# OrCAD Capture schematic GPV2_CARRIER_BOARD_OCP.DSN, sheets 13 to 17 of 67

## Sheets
13 013 MEZZ CONN EXTENSION: size C
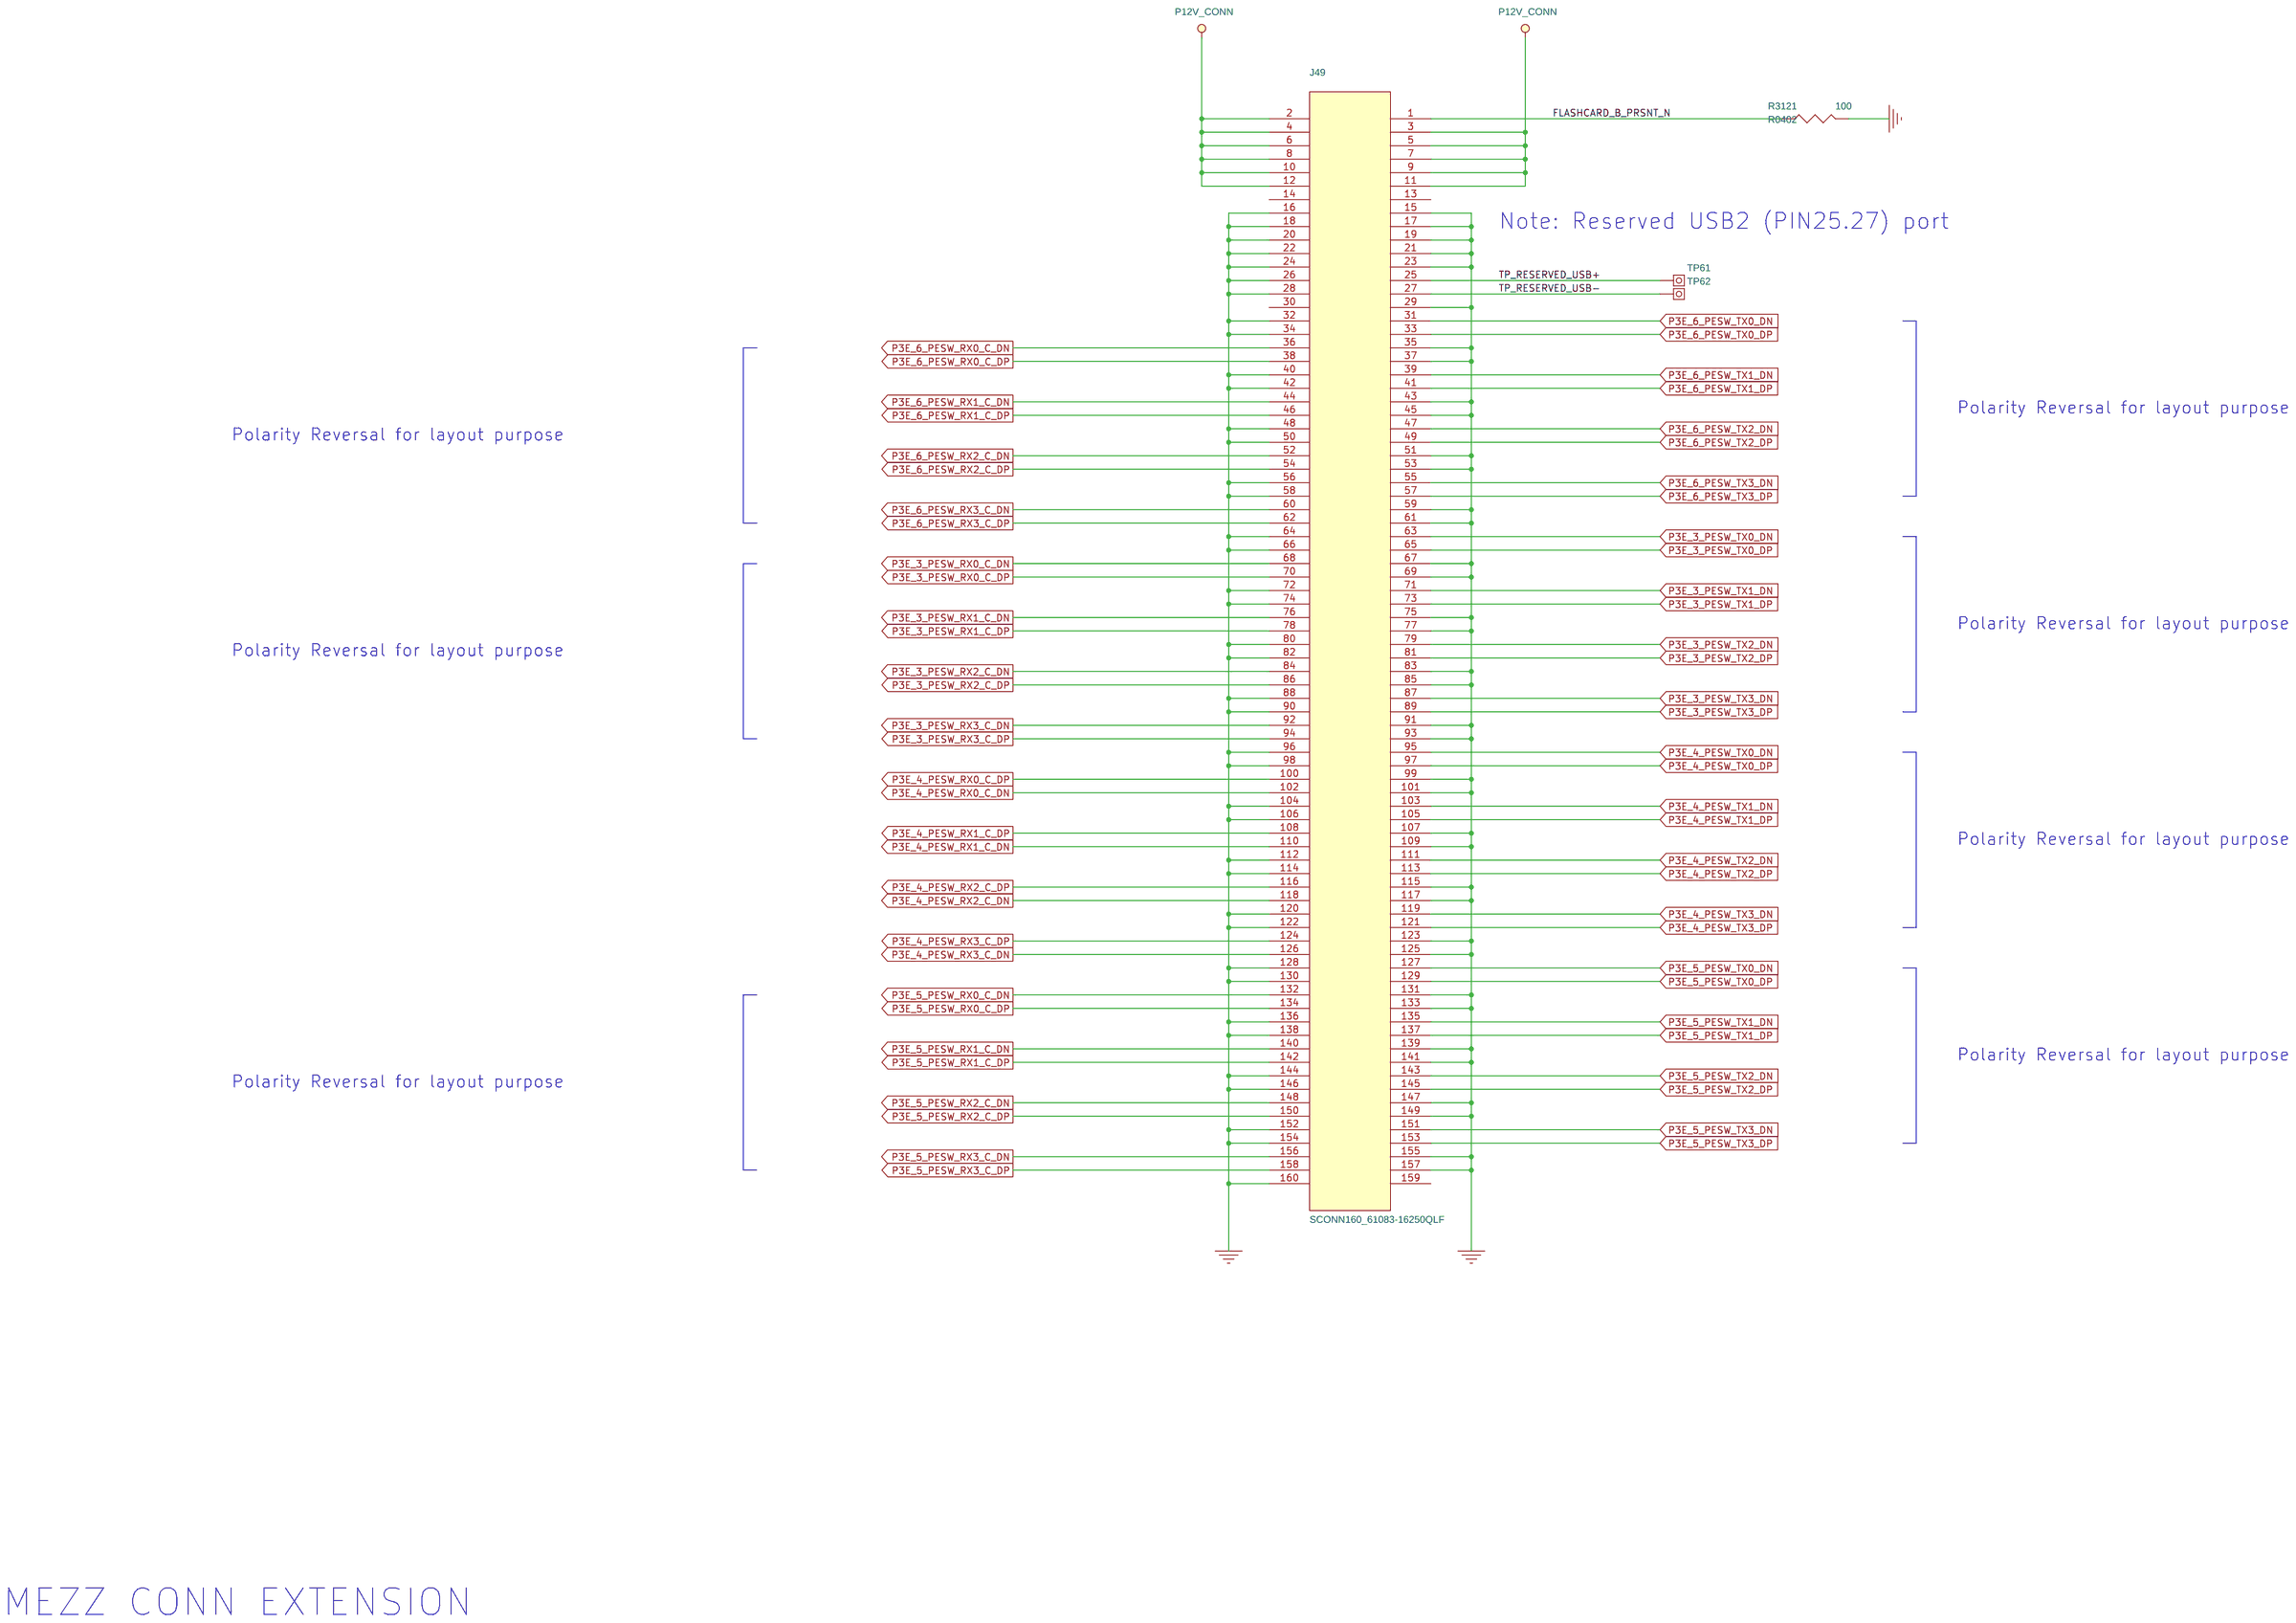
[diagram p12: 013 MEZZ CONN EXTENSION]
14 014 PCIE SWITCH (STACK1-2): size C
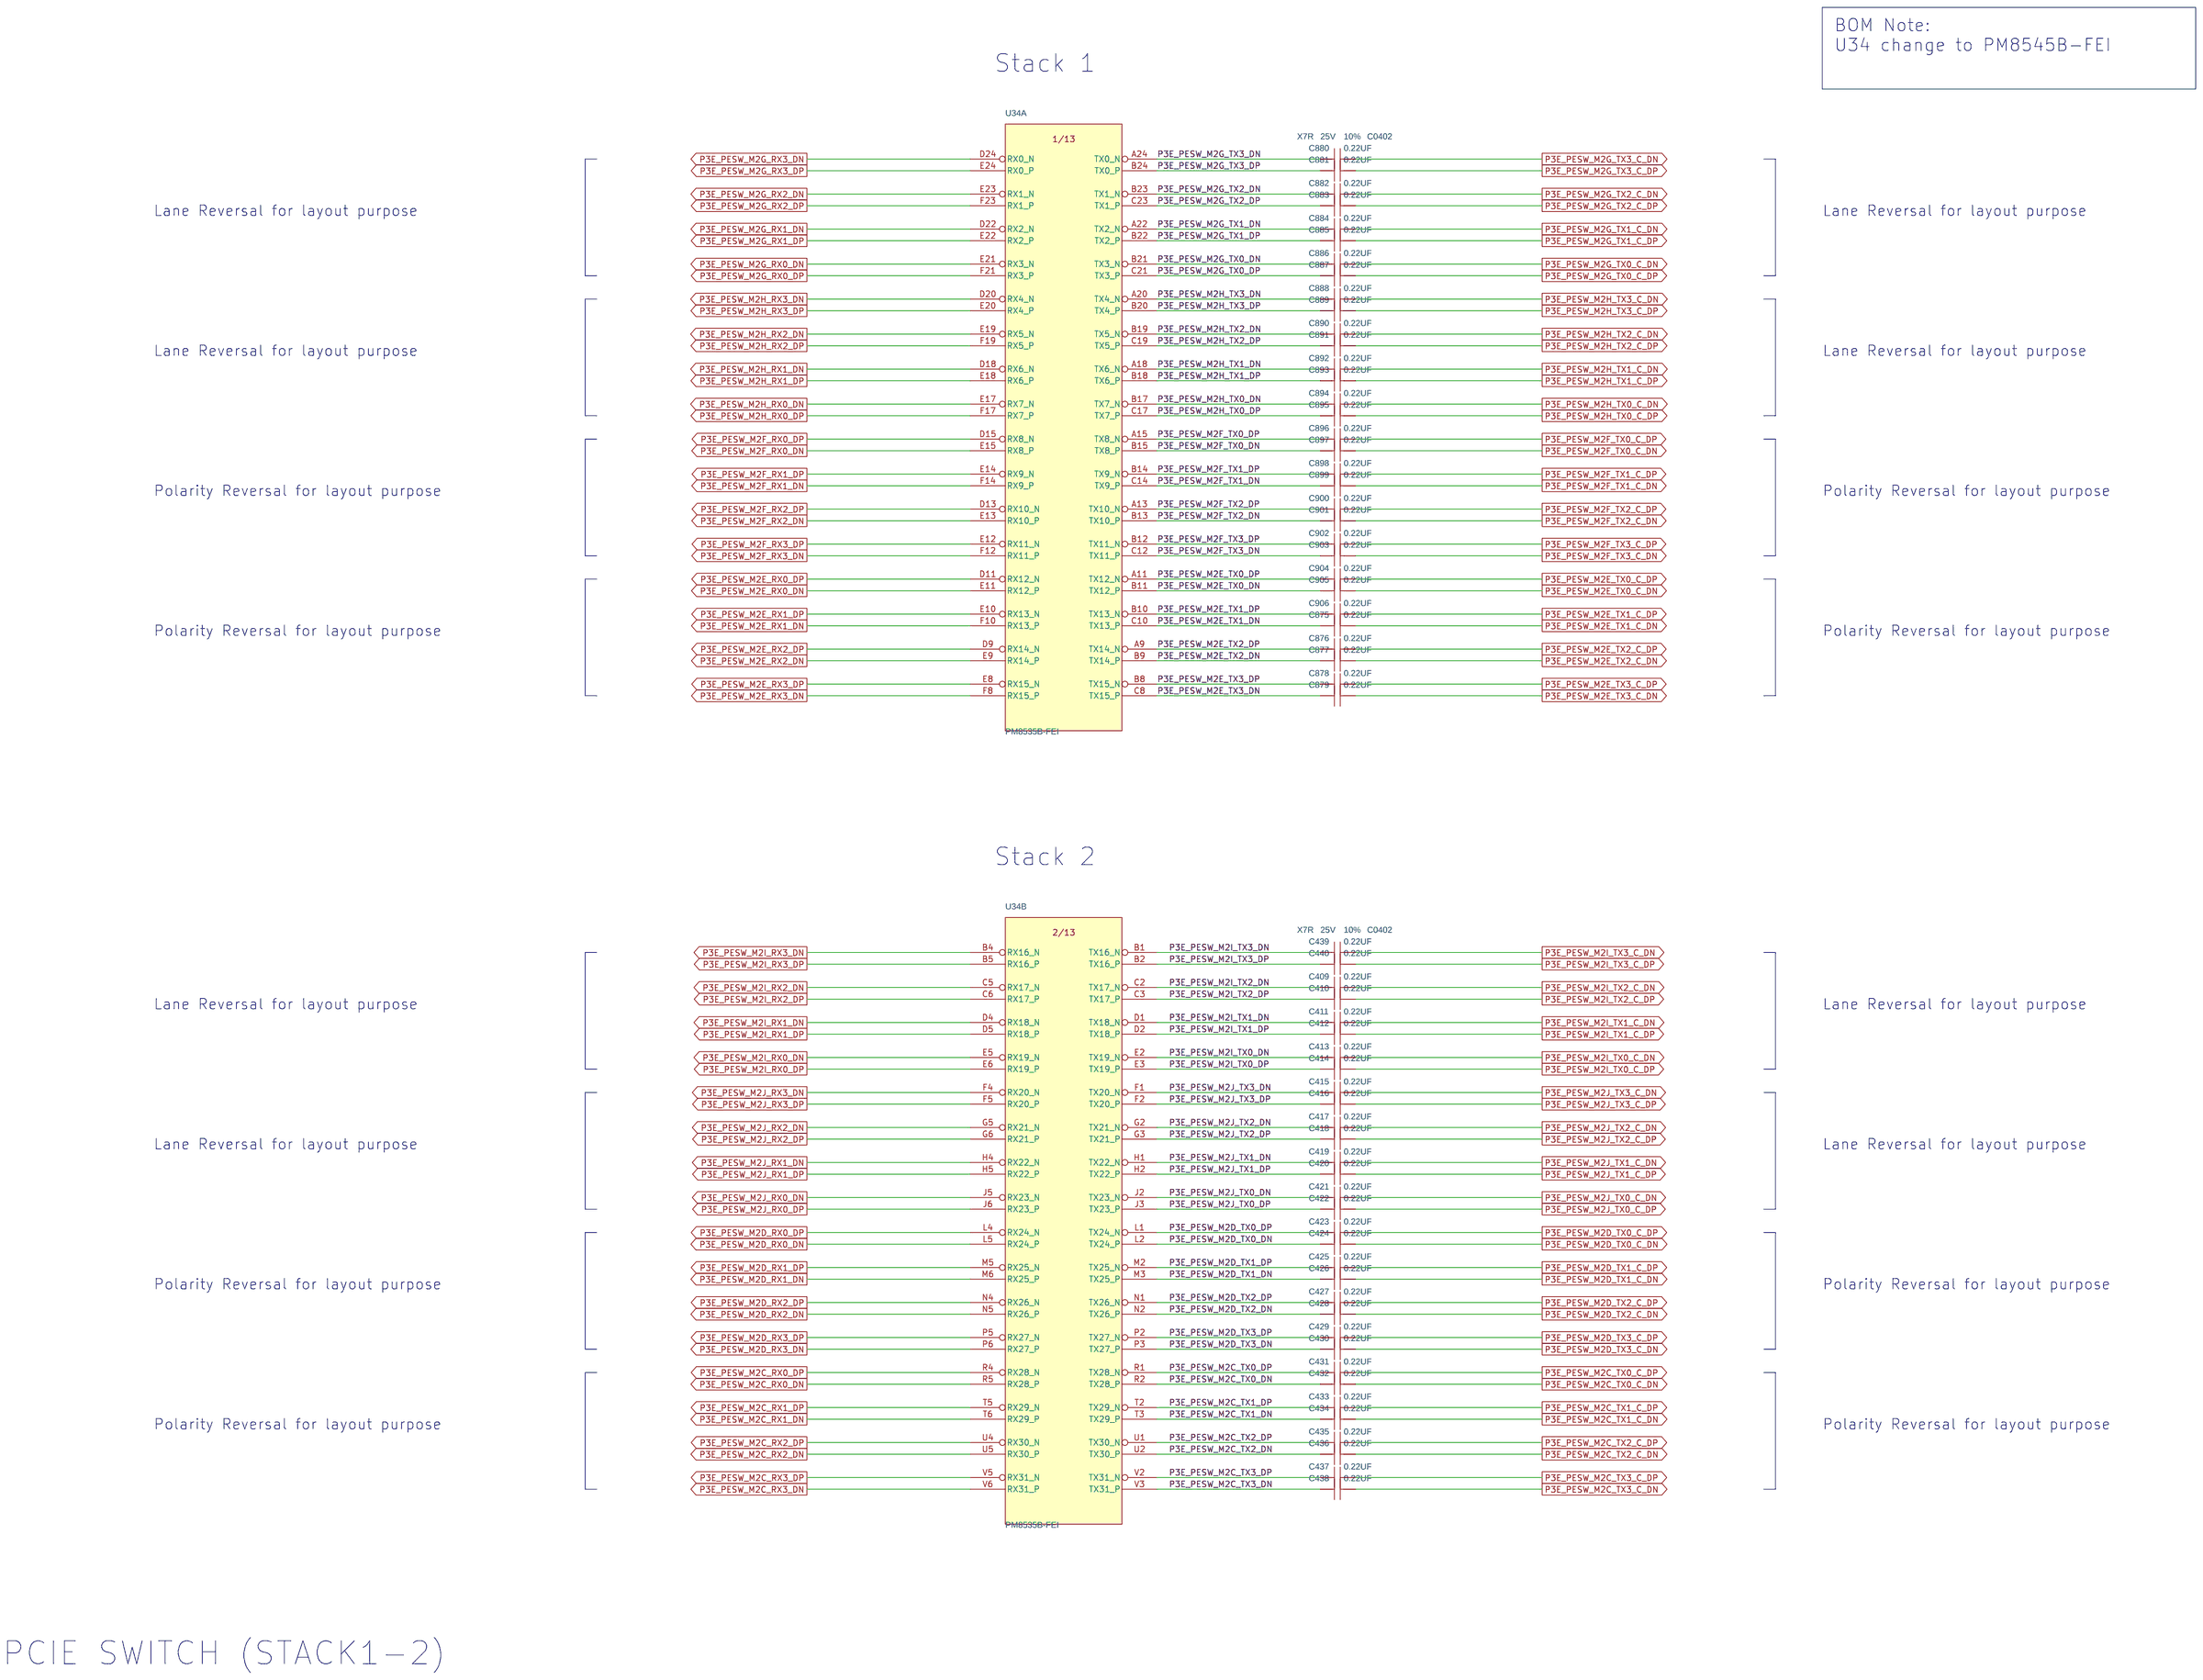
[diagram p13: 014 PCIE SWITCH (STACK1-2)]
15 015 PCIE SWITCH (STACK3-4): size C
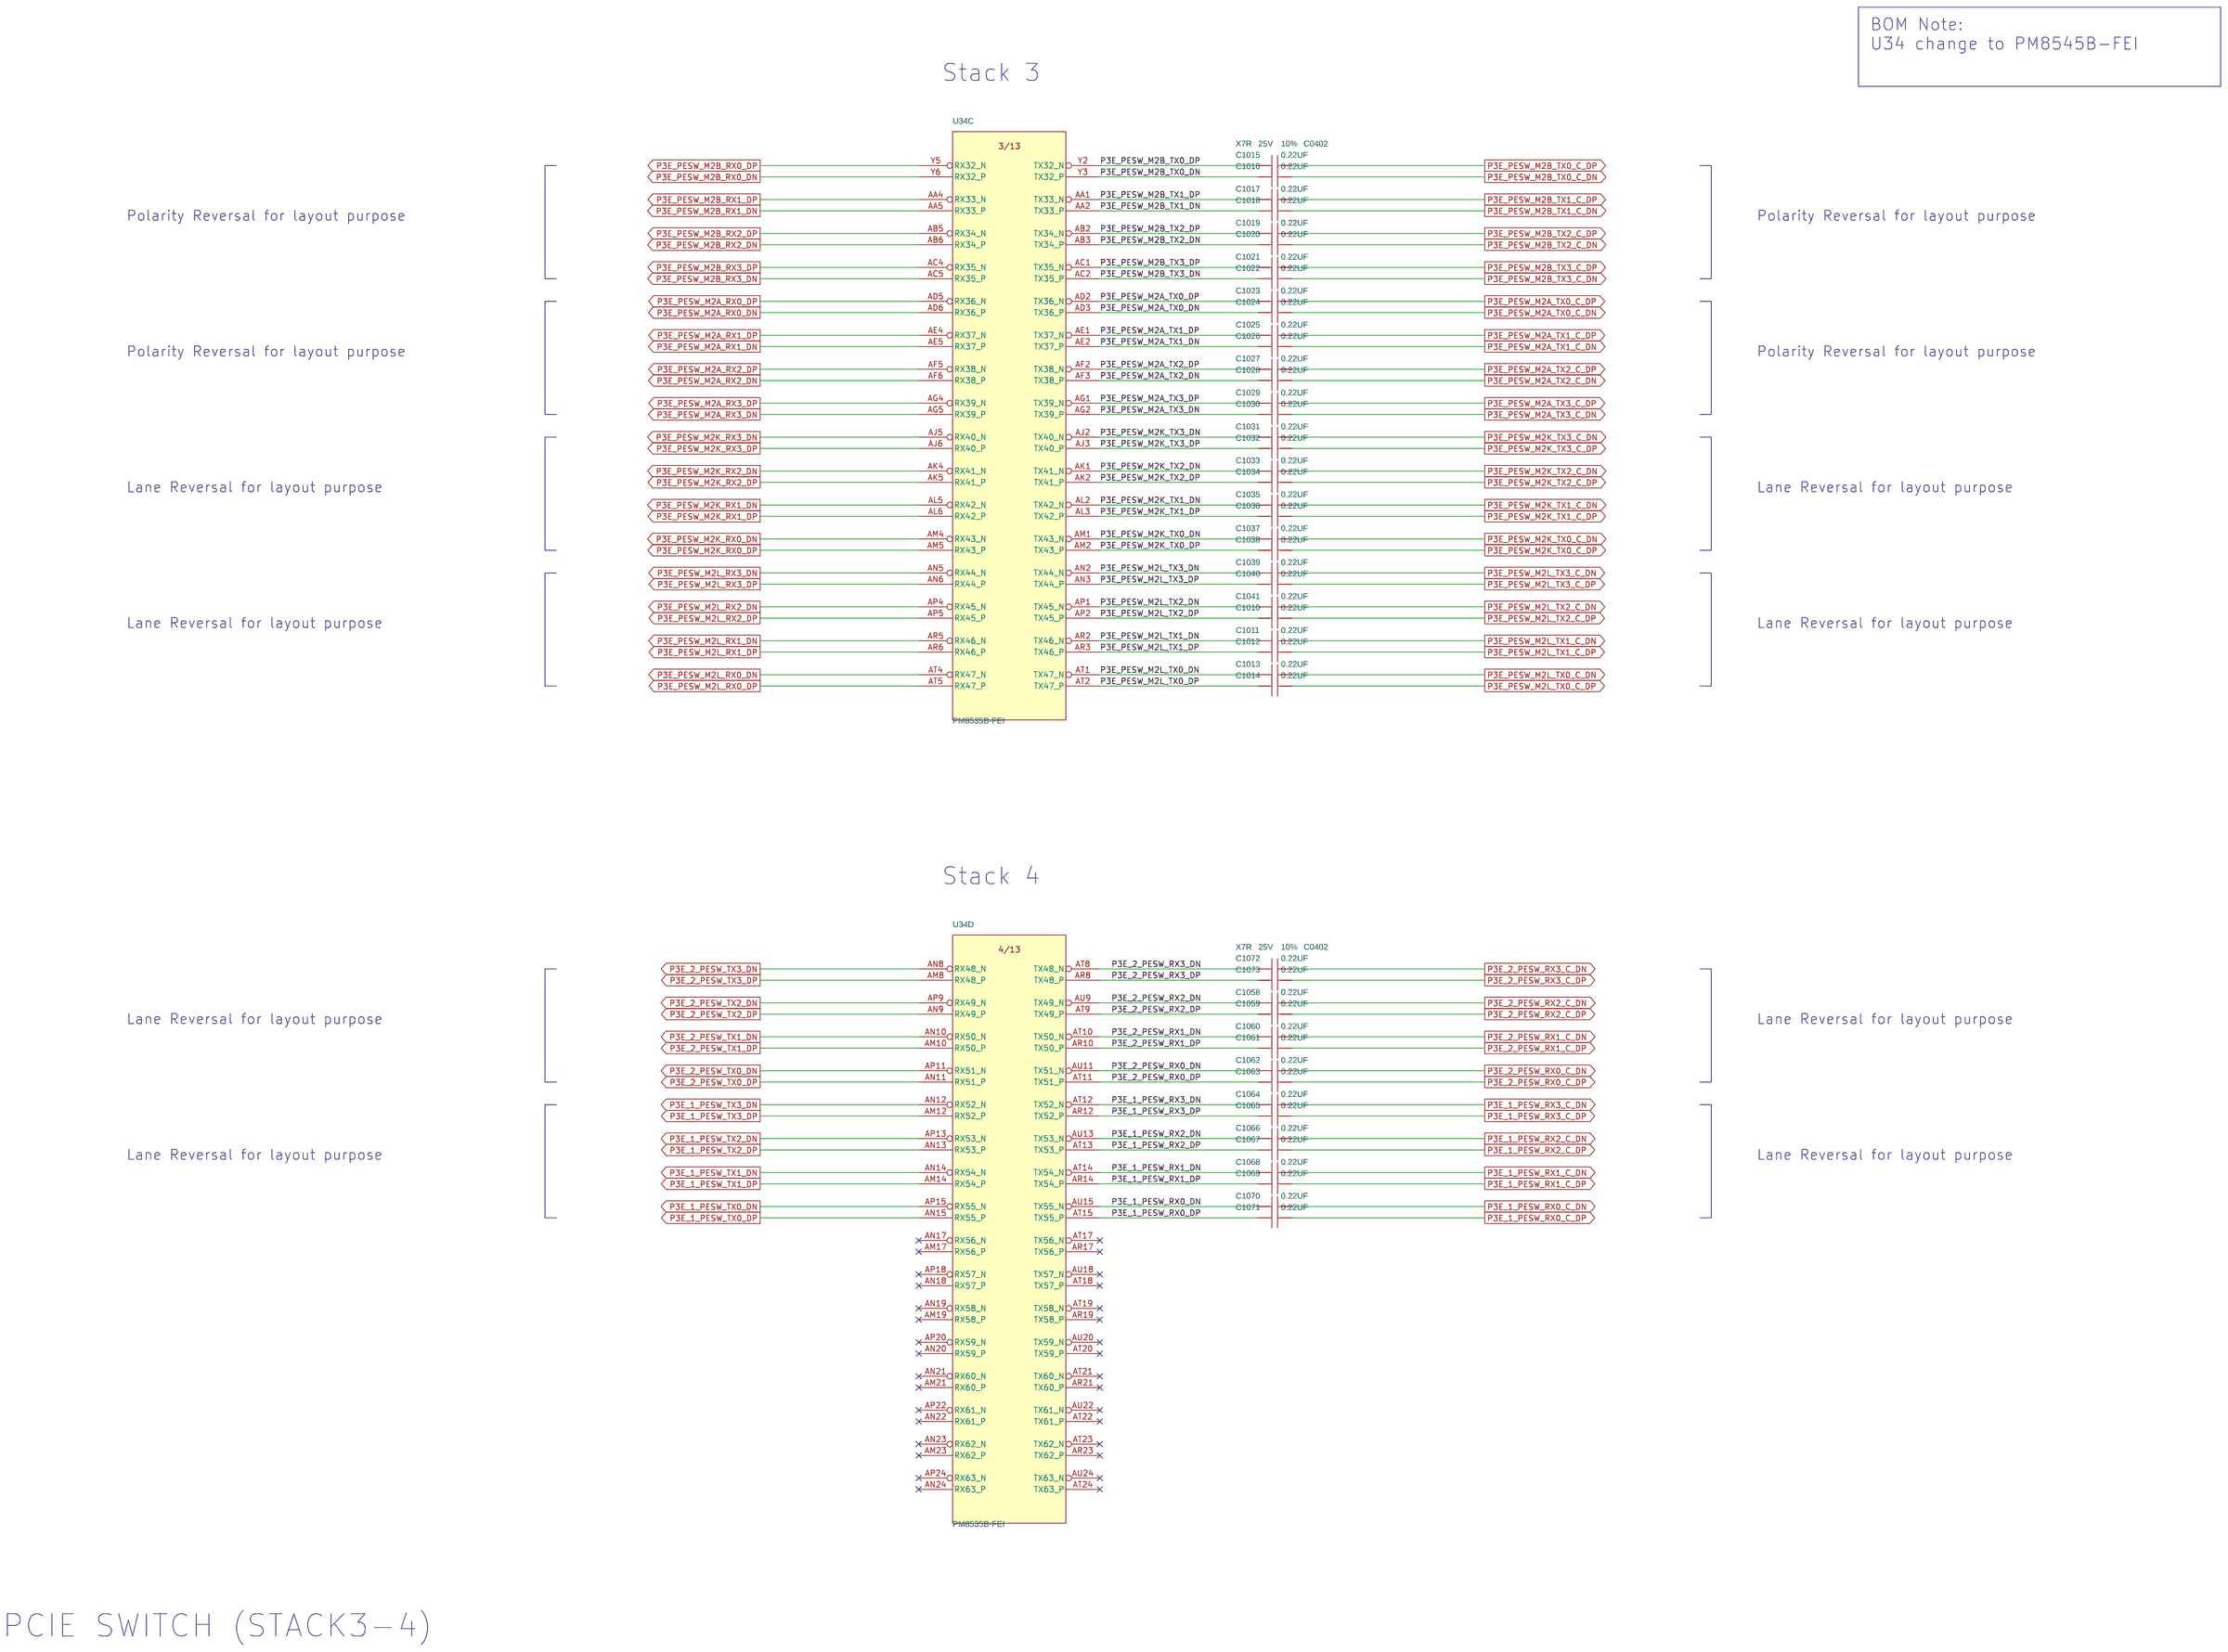
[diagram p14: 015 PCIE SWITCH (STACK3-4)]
16 016 PCIE SWITCH (STACK5): size C
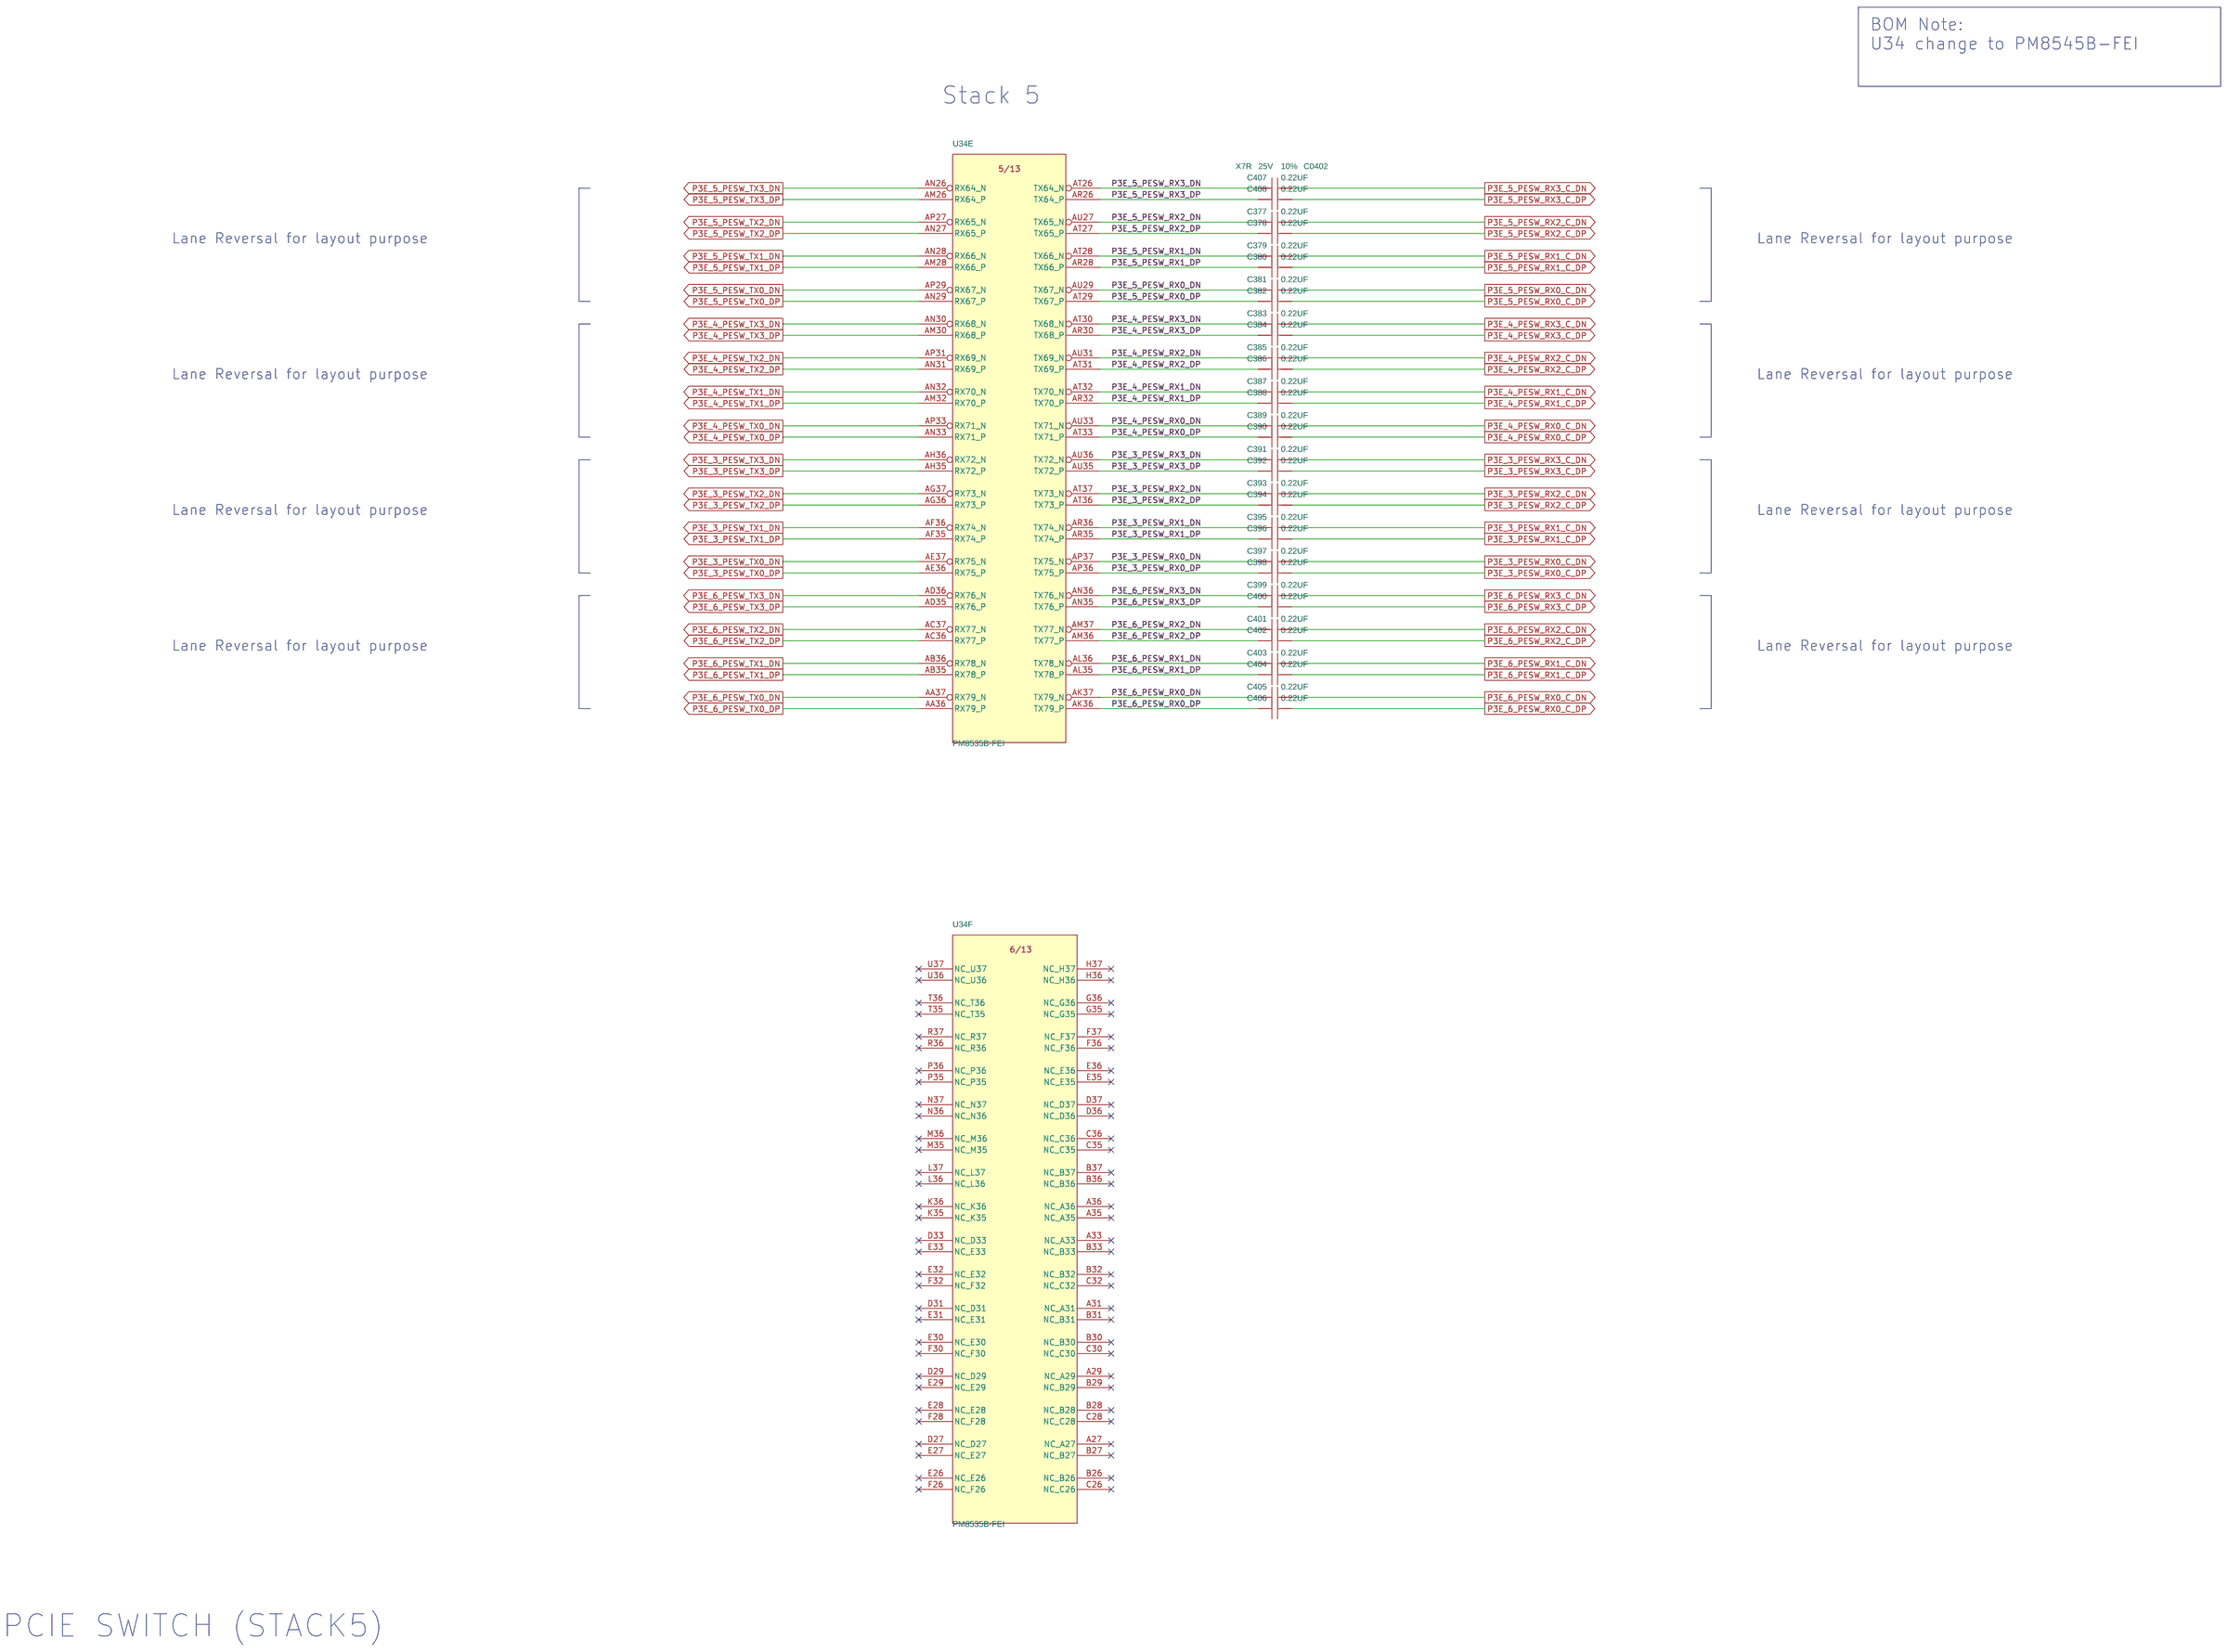
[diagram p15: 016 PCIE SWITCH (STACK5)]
17 018 PCIE SWITCH (GPIO): size C
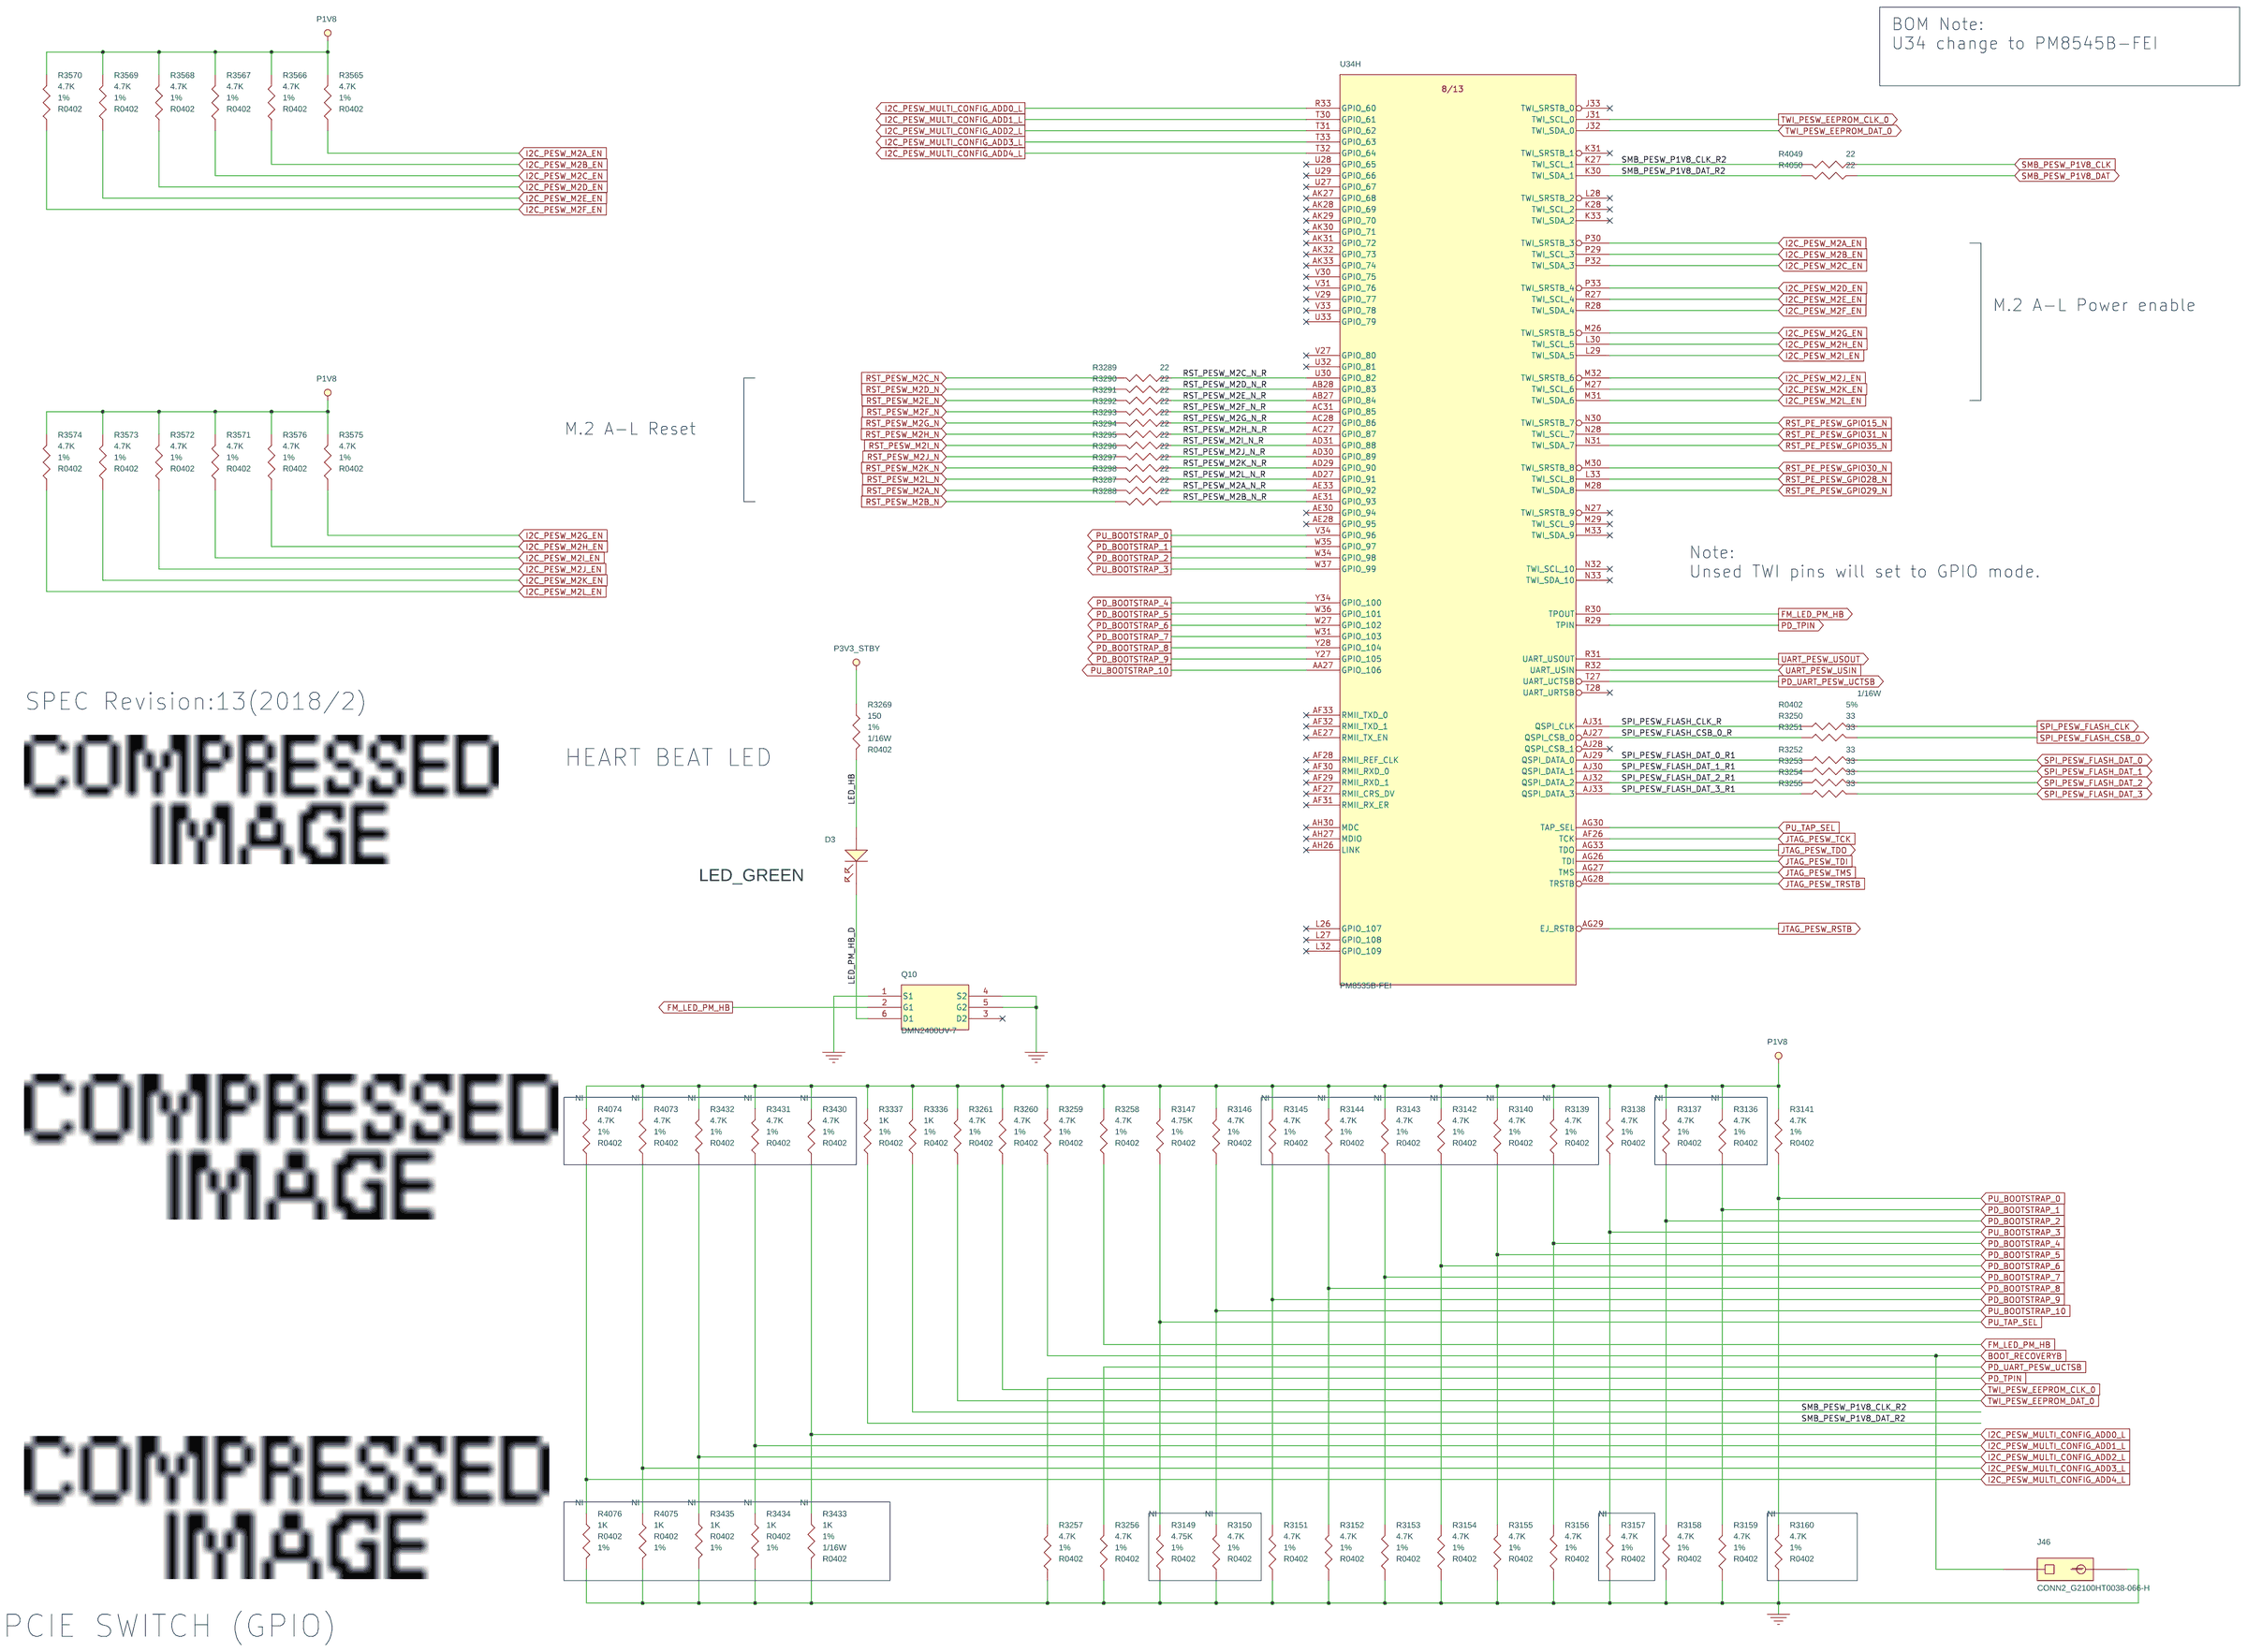
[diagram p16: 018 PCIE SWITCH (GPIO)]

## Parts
sheet 013 MEZZ CONN EXTENSION
J49  SCONN160_61083-16250QLF  [CON_M160S2H2D_P0-8W4-4_LUV]
R3121  100  [R0402]
TP61  TP  [TP26D10]
TP62  TP  [TP26D10]
sheet 014 PCIE SWITCH (STACK1-2)
C409  0.22UF  [C0402]
C410  0.22UF  [C0402]
C411  0.22UF  [C0402]
C412  0.22UF  [C0402]
C413  0.22UF  [C0402]
C414  0.22UF  [C0402]
C415  0.22UF  [C0402]
C416  0.22UF  [C0402]
C417  0.22UF  [C0402]
C418  0.22UF  [C0402]
C419  0.22UF  [C0402]
C420  0.22UF  [C0402]
C421  0.22UF  [C0402]
C422  0.22UF  [C0402]
C423  0.22UF  [C0402]
C424  0.22UF  [C0402]
C425  0.22UF  [C0402]
C426  0.22UF  [C0402]
C427  0.22UF  [C0402]
C428  0.22UF  [C0402]
C429  0.22UF  [C0402]
C430  0.22UF  [C0402]
C431  0.22UF  [C0402]
C432  0.22UF  [C0402]
C433  0.22UF  [C0402]
C434  0.22UF  [C0402]
C435  0.22UF  [C0402]
C436  0.22UF  [C0402]
C437  0.22UF  [C0402]
C438  0.22UF  [C0402]
C439  0.22UF  [C0402]
C440  0.22UF  [C0402]
C875  0.22UF  [C0402]
C876  0.22UF  [C0402]
C877  0.22UF  [C0402]
C878  0.22UF  [C0402]
C879  0.22UF  [C0402]
C880  0.22UF  [C0402]
C881  0.22UF  [C0402]
C882  0.22UF  [C0402]
C883  0.22UF  [C0402]
C884  0.22UF  [C0402]
C885  0.22UF  [C0402]
C886  0.22UF  [C0402]
C887  0.22UF  [C0402]
C888  0.22UF  [C0402]
C889  0.22UF  [C0402]
C890  0.22UF  [C0402]
C891  0.22UF  [C0402]
C892  0.22UF  [C0402]
C893  0.22UF  [C0402]
C894  0.22UF  [C0402]
C895  0.22UF  [C0402]
C896  0.22UF  [C0402]
C897  0.22UF  [C0402]
C898  0.22UF  [C0402]
C899  0.22UF  [C0402]
C900  0.22UF  [C0402]
C901  0.22UF  [C0402]
C902  0.22UF  [C0402]
C903  0.22UF  [C0402]
C904  0.22UF  [C0402]
C905  0.22UF  [C0402]
C906  0.22UF  [C0402]
sheet 015 PCIE SWITCH (STACK3-4)
C1010  0.22UF  [C0402]
C1011  0.22UF  [C0402]
C1012  0.22UF  [C0402]
C1013  0.22UF  [C0402]
C1014  0.22UF  [C0402]
C1015  0.22UF  [C0402]
C1016  0.22UF  [C0402]
C1017  0.22UF  [C0402]
C1018  0.22UF  [C0402]
C1019  0.22UF  [C0402]
C1020  0.22UF  [C0402]
C1021  0.22UF  [C0402]
C1022  0.22UF  [C0402]
C1023  0.22UF  [C0402]
C1024  0.22UF  [C0402]
C1025  0.22UF  [C0402]
C1026  0.22UF  [C0402]
C1027  0.22UF  [C0402]
C1028  0.22UF  [C0402]
C1029  0.22UF  [C0402]
C1030  0.22UF  [C0402]
C1031  0.22UF  [C0402]
C1032  0.22UF  [C0402]
C1033  0.22UF  [C0402]
C1034  0.22UF  [C0402]
C1035  0.22UF  [C0402]
C1036  0.22UF  [C0402]
C1037  0.22UF  [C0402]
C1038  0.22UF  [C0402]
C1039  0.22UF  [C0402]
C1040  0.22UF  [C0402]
C1041  0.22UF  [C0402]
C1058  0.22UF  [C0402]
C1059  0.22UF  [C0402]
C1060  0.22UF  [C0402]
C1061  0.22UF  [C0402]
C1062  0.22UF  [C0402]
C1063  0.22UF  [C0402]
C1064  0.22UF  [C0402]
C1065  0.22UF  [C0402]
C1066  0.22UF  [C0402]
C1067  0.22UF  [C0402]
C1068  0.22UF  [C0402]
C1069  0.22UF  [C0402]
C1070  0.22UF  [C0402]
C1071  0.22UF  [C0402]
C1072  0.22UF  [C0402]
C1073  0.22UF  [C0402]
sheet 016 PCIE SWITCH (STACK5)
C377  0.22UF  [C0402]
C378  0.22UF  [C0402]
C379  0.22UF  [C0402]
C380  0.22UF  [C0402]
C381  0.22UF  [C0402]
C382  0.22UF  [C0402]
C383  0.22UF  [C0402]
C384  0.22UF  [C0402]
C385  0.22UF  [C0402]
C386  0.22UF  [C0402]
C387  0.22UF  [C0402]
C388  0.22UF  [C0402]
C389  0.22UF  [C0402]
C390  0.22UF  [C0402]
C391  0.22UF  [C0402]
C392  0.22UF  [C0402]
C393  0.22UF  [C0402]
C394  0.22UF  [C0402]
C395  0.22UF  [C0402]
C396  0.22UF  [C0402]
C397  0.22UF  [C0402]
C398  0.22UF  [C0402]
C399  0.22UF  [C0402]
C400  0.22UF  [C0402]
C401  0.22UF  [C0402]
C402  0.22UF  [C0402]
C403  0.22UF  [C0402]
C404  0.22UF  [C0402]
C405  0.22UF  [C0402]
C406  0.22UF  [C0402]
C407  0.22UF  [C0402]
C408  0.22UF  [C0402]
sheet 017 PCIE SWITCH (CLOCKS/RESET)
U34  PM8535B-FEI  [BGA1311_1_37-5X37-5]  (sections A,B,C,D,E,F,G,H,I,J,K,L,M)
sheet 018 PCIE SWITCH (GPIO)
D3  LED_GREEN  [LED_1921]
J46  CONN2_G2100HT0038-066-H  [HEADER1X2XJ_H339]
Q10  DMN2400UV-7  [SOT563-6XA]
R3136  4.7K  [R0402]
R3137  4.7K  [R0402]
R3138  4.7K  [R0402]
R3139  4.7K  [R0402]
R3140  4.7K  [R0402]
R3141  4.7K  [R0402]
R3142  4.7K  [R0402]
R3143  4.7K  [R0402]
R3144  4.7K  [R0402]
R3145  4.7K  [R0402]
R3146  4.7K  [R0402]
R3147  4.75K  [R0402]
R3149  4.75K  [R0402]
R3150  4.7K  [R0402]
R3151  4.7K  [R0402]
R3152  4.7K  [R0402]
R3153  4.7K  [R0402]
R3154  4.7K  [R0402]
R3155  4.7K  [R0402]
R3156  4.7K  [R0402]
R3157  4.7K  [R0402]
R3158  4.7K  [R0402]
R3159  4.7K  [R0402]
R3160  4.7K  [R0402]
R3250  33  [R0402]
R3251  33  [R0402]
R3252  33  [R0402]
R3253  33  [R0402]
R3254  33  [R0402]
R3255  33  [R0402]
R3256  4.7K  [R0402]
R3257  4.7K  [R0402]
R3258  4.7K  [R0402]
R3259  4.7K  [R0402]
R3260  4.7K  [R0402]
R3261  4.7K  [R0402]
R3269  150  [R0402]
R3287  22  [R0402]
R3288  22  [R0402]
R3289  22  [R0402]
R3290  22  [R0402]
R3291  22  [R0402]
R3292  22  [R0402]
R3293  22  [R0402]
R3294  22  [R0402]
R3295  22  [R0402]
R3296  22  [R0402]
R3297  22  [R0402]
R3298  22  [R0402]
R3336  1K  [R0402]
R3337  1K  [R0402]
R3430  4.7K  [R0402]
R3431  4.7K  [R0402]
R3432  4.7K  [R0402]
R3433  1K  [R0402]
R3434  1K  [R0402]
R3435  1K  [R0402]
R3565  4.7K  [R0402]
R3566  4.7K  [R0402]
R3567  4.7K  [R0402]
R3568  4.7K  [R0402]
R3569  4.7K  [R0402]
R3570  4.7K  [R0402]
R3571  4.7K  [R0402]
R3572  4.7K  [R0402]
R3573  4.7K  [R0402]
R3574  4.7K  [R0402]
R3575  4.7K  [R0402]
R3576  4.7K  [R0402]
R4049  22  [R0402]
R4050  22  [R0402]
R4073  4.7K  [R0402]
R4074  4.7K  [R0402]
R4075  1K  [R0402]
R4076  1K  [R0402]

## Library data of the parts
J49 = SCONN160_6108316150QLF: CONN SMD HEADER 160P 2R MS(P0.8,H5.7); CLASS: IO; ESD_CDM: N/A; ESD_HBM: N/A; ESD_MM: N/A; MATERIAL: IO; MSD: NA; Manuf_PN: 61083-16250QLF; Manuf_name: AMPHENOL EAST ASIA LIMITED (Amphenol-TCS) (Shangh; Manuftr: APL; PIN_LENGTH_LONG_PIN: 32 MILS; PIN_LENGTH_SHORT_PIN: 32 MILS; Part_Type: *LF_Connector
R3121 = R: RES CHIP 100 1/16W +-5% (0402); CLASS: DISCRETE; MATERIAL: CHIP; Manuf_PN: RR0510S-101-JN; Manuf_name: CYNTEC CO.. LTD.; Manuftr: CYN; Part_Type: *LF_Resistor; TOLERANCE: 5%; WATTAGE: 1/16W
TP61 TP62 = TP: TEST POINT (TP26D10) DIP(DRILL10MILS); ALT_SYMBOLS: TOP:TP26D10;BOTTOM:TP30D10; CLASS: IO; DIP_SMD: DIP; MATERIAL: MISC; Not_insert: NI; Part_Type: Misc
C377-C440 C875-C906 C1010-C1041 C1058-C1073 = CAP_NP: CAP CHIP 0.22U 25V(10%,X7R,0402); CLASS: DISCRETE; MATERIAL: X7R; Manuf_PN: TMK105B7224KV-FR; Manuf_name: TAIYO YUDEN CO.,LTD; Manuftr: TAY; Part_Type: *LF_C0402; TOLERANCE: 10%; VOLTAGE: 25V
U34 = PM8535BFEI: IC CTRL(1311P)PM8535B-FEI(FCBGA); CLASS: IC; ESD_CDM: N/A; ESD_HBM: N/A; ESD_MM: N/A; MATERIAL: IC; MSD: NA; Manuf_name: Microsemi Corporation ( Microsemi Taiwan); Manuftr: MST; PIN_LENGTH_LONG_PIN: 0 MILS; PIN_LENGTH_SHORT_PIN: 0 MILS; Part_Type: *LF_Chipset
D3 = LED_0: LED SMD(2P) GREEN(19-213/GVC-AMNB/3T); CLASS: IC; MATERIAL: IC; Manuf_PN: 19-213/GVC-AMNB/3T; Manuf_name: EVERLIGHT (EVERLIGHT ELECTRONICS CO., LTD. ); Manuftr: EVL; Part_Type: *LF_Semiconductor
J46 = DIP_2PIN: CONN DIP HEADER 2P 1R MS(P2.54,H8.6); CLASS: IO; DIP_SMD: DIP; ESD_CDM: NA; ESD_HBM: NA; ESD_MM: NA; MATERIAL: IO; MSD: NA; Manuf_PN: G2100HT0038-066-H; Manuf_name: WIESON ELECTRONIC CO.,LTD. (Wieson International; Manuftr: WSE; PIN_LENGTH_LONG_PIN: 119 MILS; PIN_LENGTH_SHORT_PIN: 119 MILS; Part_Type: *LF_Connector
Q10 = MOSFET_DUAL_6P: TRANS MOS DMN2400UV-7(20V,1.33A,0.53W); CLASS: IC; MATERIAL: IC; Manuf_name: DIODES TAIWAN CO.,LTD.(Kai Hong Shanghai); Manuftr: DDS; Part_Type: *LF_Semiconductor
R3136 R3137 R3139 R3140 R3142-R3145 R3150 R3157 R3160 R3430-R3432 R4073 R4074 = R: RES CHIP 4.7K 1/16W +-1%(0402); CLASS: DISCRETE; MATERIAL: CHIP; Manuf_PN: RTT024701FTH; Manuf_name: RALEC ELECTRONIC CO.; Manuftr: RLC; Not_insert: NI; Part_Type: *LF_Resistor; TOLERANCE: 1%; WATTAGE: 1/16W
R3138 R3141 R3146 R3151-R3156 R3158 R3159 R3256-R3261 R3565-R3576 = R: RES CHIP 4.7K 1/16W +-1%(0402); CLASS: DISCRETE; MATERIAL: CHIP; Manuf_PN: RTT024701FTH; Manuf_name: RALEC ELECTRONIC CO.; Manuftr: RLC; Part_Type: *LF_Resistor; TOLERANCE: 1%; WATTAGE: 1/16W
R3147 = R: RES CHIP 4.75K 1/16W +-1%(0402); CLASS: DISCRETE; MATERIAL: CHIP; Manuf_PN: RR0510S-4751-FN; Manuf_name: CYNTEC CO.. LTD.; Manuftr: CYN; Part_Type: *LF_Resistor; TOLERANCE: 1%; WATTAGE: 1/16W
R3149 = R: RES CHIP 4.75K 1/16W +-1%(0402); CLASS: DISCRETE; MATERIAL: CHIP; Manuf_PN: RR0510S-4751-FN; Manuf_name: CYNTEC CO.. LTD.; Manuftr: CYN; Not_insert: NI; Part_Type: *LF_Resistor; TOLERANCE: 1%; WATTAGE: 1/16W
R3250-R3255 = R: RES CHIP 33 1/16W +-5% (0402); CLASS: DISCRETE; MATERIAL: CHIP; Manuf_PN: RR0510S-330-JN; Manuf_name: CYNTEC CO.. LTD.; Manuftr: CYN; Part_Type: *LF_Resistor; TOLERANCE: 5%; WATTAGE: 1/16W
R3269 = R: RES CHIP 150 1/16W +-1%(0402); CLASS: DISCRETE; MATERIAL: CHIP; Manuf_PN: RR0510S-151-FN; Manuf_name: CYNTEC CO.. LTD.; Manuftr: CYN; Part_Type: *LF_Resistor; TOLERANCE: 1%; WATTAGE: 1/16W
R3287-R3298 R4049 R4050 = R: RES CHIP 22 1/16W +-1%(0402); BOM: AST2300; CLASS: DISCRETE; MATERIAL: CHIP; Manuf_PN: CR0222R0F002S; Manuf_name: RTECH TECHNOLOGY CO..LTD. (Compostar); Manufacturer: CYN; Manuftr: RHT; Part_Type: *LF_Resistor; TOLERANCE: 1%; WATTAGE: 1/16W
R3336 R3337 = R: RES CHIP 1K 1/16W +-1% (0402); CLASS: DISCRETE; MATERIAL: CHIP; Manuf_PN: RR0510S-102-FN; Manuf_name: CYNTEC CO.. LTD.; Manuftr: CYN; Part_Type: *LF_Resistor; TOLERANCE: 1%; WATTAGE: 1/16W
R3433-R3435 R4075 R4076 = R: RES CHIP 1K 1/16W +-1% (0402); CLASS: DISCRETE; MATERIAL: CHIP; Manuf_PN: RR0510S-102-FN; Manuf_name: CYNTEC CO.. LTD.; Manuftr: CYN; Not_insert: NI; Part_Type: *LF_Resistor; TOLERANCE: 1%; WATTAGE: 1/16W

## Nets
GND: J46.2 J49.15 J49.16 J49.17 J49.18 J49.19 J49.20 J49.21 J49.22 J49.23 J49.24 J49.26 J49.28 J49.29 J49.32 J49.34 J49.35 J49.37 J49.40 J49.42 J49.43 J49.45 J49.48 J49.50 J49.51 J49.53 J49.56 J49.58 J49.59 J49.61 J49.64 J49.66 J49.67 J49.69 J49.72 J49.74 J49.75 J49.77 J49.80 J49.82 J49.83 J49.85 J49.88 J49.90 J49.91 J49.93 J49.96 J49.98 J49.99 J49.101 J49.104 J49.106 J49.107 J49.109 J49.112 J49.114 J49.115 J49.117 J49.120 J49.122 J49.123 J49.125 J49.128 J49.130 J49.131 J49.133 J49.136 J49.138 J49.139 J49.141 J49.144 J49.146 J49.147 J49.149 J49.152 J49.154 J49.155 J49.157 J49.160 Q10.1(S1) Q10.4(S2) Q10.5(G2) R3121.2 R3149.1 R3150.1 R3151.1 R3152.1 R3153.1 R3154.1 R3155.1 R3156.1 R3157.1 R3158.1 R3159.1 R3160.1 R3256.1 R3257.1 R3433.2 R3434.2 R3435.2 R4075.2 R4076.2 ; also on sheet 12 18 19 20 21 22 23 24 25 26 27 28 29 30 31 32 33 34 35 36 37 38 39 40 41 42 43 44 45 46 47 48 49 50 52 53 54 55 56 57 58 61 62 63 64 65 66 67
P1V8: R3136.2 R3137.2 R3138.2 R3139.2 R3140.2 R3141.2 R3142.2 R3143.2 R3144.2 R3145.2 R3146.2 R3147.2 R3258.2 R3259.2 R3260.2 R3261.2 R3336.2 R3337.2 R3430.2 R3431.2 R3432.2 R3565.2 R3566.2 R3567.2 R3568.2 R3569.2 R3570.2 R3571.2 R3572.2 R3573.2 R3574.2 R3575.2 R3576.2 R4073.2 R4074.2 ; also on sheet 18 19 22 23 24 25 26 27 28 29 30 31 32 33 34 35 36 37 44 49 50 53 58 62 65 67
P3V3_STBY: R3269.1 ; also on sheet 12 18 19 20 22 23 24 25 26 27 28 29 30 31 32 33 34 35 36 37 38 39 40 41 42 43 44 45 46 47 48 49 50 52 53 54 55 56 57 58 61 67
P12V_CONN: J49.2 J49.3 J49.4 J49.5 J49.6 J49.7 J49.8 J49.9 J49.10 J49.11 J49.12 ; also on sheet 12 61
BOOT_RECOVERYB: J46.1 R3259.1 ; also on sheet 67
FLASHCARD_B_PRSNT_N: J49.1 R3121.1
FM_LED_PM_HB: Q10.2(G1) R3258.1 U34.R30(TPOUT)
I2C_PESW_M2A_EN: R3565.1 U34.P30(TWI_SRSTB_3) ; also on sheet 23
I2C_PESW_M2B_EN: R3566.1 U34.P29(TWI_SCL_3) ; also on sheet 23
I2C_PESW_M2C_EN: R3567.1 U34.P32(TWI_SDA_3) ; also on sheet 23
I2C_PESW_M2D_EN: R3568.1 U34.P33(TWI_SRSTB_4) ; also on sheet 23
I2C_PESW_M2E_EN: R3569.1 U34.R27(TWI_SCL_4) ; also on sheet 23
I2C_PESW_M2F_EN: R3570.1 U34.R28(TWI_SDA_4) ; also on sheet 23
I2C_PESW_M2G_EN: R3575.1 U34.M26(TWI_SRSTB_5) ; also on sheet 23
I2C_PESW_M2H_EN: R3576.1 U34.L30(TWI_SCL_5) ; also on sheet 23
I2C_PESW_M2I_EN: R3571.1 U34.L29(TWI_SDA_5) ; also on sheet 23
I2C_PESW_M2J_EN: R3572.1 U34.M32(TWI_SRSTB_6) ; also on sheet 23
I2C_PESW_M2K_EN: R3573.1 U34.M27(TWI_SCL_6) ; also on sheet 23
I2C_PESW_M2L_EN: R3574.1 U34.M31(TWI_SDA_6) ; also on sheet 23
I2C_PESW_MULTI_CONFIG_ADD0_L: R3430.1 R3433.1 U34.R33(GPIO_60) ; also on sheet 22
I2C_PESW_MULTI_CONFIG_ADD1_L: R3431.1 R3434.1 U34.T30(GPIO_61) ; also on sheet 22
I2C_PESW_MULTI_CONFIG_ADD2_L: R3432.1 R3435.1 U34.T31(GPIO_62) ; also on sheet 22
I2C_PESW_MULTI_CONFIG_ADD3_L: R4073.1 R4075.1 U34.T33(GPIO_63) ; also on sheet 22
I2C_PESW_MULTI_CONFIG_ADD4_L: R4074.1 R4076.1 U34.T32(GPIO_64) ; also on sheet 22
JTAG_PESW_RSTB: U34.AG29(EJ_RSTB) ; also on sheet 62
JTAG_PESW_TCK: U34.AF26(TCK) ; also on sheet 62
JTAG_PESW_TDI: U34.AG26(TDI) ; also on sheet 62
JTAG_PESW_TDO: U34.AG33(TDO) ; also on sheet 62
JTAG_PESW_TMS: U34.AG27(TMS) ; also on sheet 62
JTAG_PESW_TRSTB: U34.AG28(TRSTB) ; also on sheet 62
LED_HB: D3.A R3269.2
LED_PM_HB_D: D3.C Q10.6(D1)
P3E_1_PESW_RX0_C_DN: C1070.2 ; also on sheet 12
P3E_1_PESW_RX0_C_DP: C1071.2 ; also on sheet 12
P3E_1_PESW_RX0_DN: C1070.1 U34.AU15(TX55_N)
P3E_1_PESW_RX0_DP: C1071.1 U34.AT15(TX55_P)
P3E_1_PESW_RX1_C_DN: C1068.2 ; also on sheet 12
P3E_1_PESW_RX1_C_DP: C1069.2 ; also on sheet 12
P3E_1_PESW_RX1_DN: C1068.1 U34.AT14(TX54_N)
P3E_1_PESW_RX1_DP: C1069.1 U34.AR14(TX54_P)
P3E_1_PESW_RX2_C_DN: C1066.2 ; also on sheet 12
P3E_1_PESW_RX2_C_DP: C1067.2 ; also on sheet 12
P3E_1_PESW_RX2_DN: C1066.1 U34.AU13(TX53_N)
P3E_1_PESW_RX2_DP: C1067.1 U34.AT13(TX53_P)
P3E_1_PESW_RX3_C_DN: C1064.2 ; also on sheet 12
P3E_1_PESW_RX3_C_DP: C1065.2 ; also on sheet 12
P3E_1_PESW_RX3_DN: C1064.1 U34.AT12(TX52_N)
P3E_1_PESW_RX3_DP: C1065.1 U34.AR12(TX52_P)
P3E_1_PESW_TX0_DN: U34.AP15(RX55_N) ; also on sheet 12
P3E_1_PESW_TX0_DP: U34.AN15(RX55_P) ; also on sheet 12
P3E_1_PESW_TX1_DN: U34.AN14(RX54_N) ; also on sheet 12
P3E_1_PESW_TX1_DP: U34.AM14(RX54_P) ; also on sheet 12
P3E_1_PESW_TX2_DN: U34.AP13(RX53_N) ; also on sheet 12
P3E_1_PESW_TX2_DP: U34.AN13(RX53_P) ; also on sheet 12
P3E_1_PESW_TX3_DN: U34.AN12(RX52_N) ; also on sheet 12
P3E_1_PESW_TX3_DP: U34.AM12(RX52_P) ; also on sheet 12
P3E_2_PESW_RX0_C_DN: C1062.2 ; also on sheet 12
P3E_2_PESW_RX0_C_DP: C1063.2 ; also on sheet 12
P3E_2_PESW_RX0_DN: C1062.1 U34.AU11(TX51_N)
P3E_2_PESW_RX0_DP: C1063.1 U34.AT11(TX51_P)
P3E_2_PESW_RX1_C_DN: C1060.2 ; also on sheet 12
P3E_2_PESW_RX1_C_DP: C1061.2 ; also on sheet 12
P3E_2_PESW_RX1_DN: C1060.1 U34.AT10(TX50_N)
P3E_2_PESW_RX1_DP: C1061.1 U34.AR10(TX50_P)
P3E_2_PESW_RX2_C_DN: C1058.2 ; also on sheet 12
P3E_2_PESW_RX2_C_DP: C1059.2 ; also on sheet 12
P3E_2_PESW_RX2_DN: C1058.1 U34.AU9(TX49_N)
P3E_2_PESW_RX2_DP: C1059.1 U34.AT9(TX49_P)
P3E_2_PESW_RX3_C_DN: C1072.2 ; also on sheet 12
P3E_2_PESW_RX3_C_DP: C1073.2 ; also on sheet 12
P3E_2_PESW_RX3_DN: C1072.1 U34.AT8(TX48_N)
P3E_2_PESW_RX3_DP: C1073.1 U34.AR8(TX48_P)
P3E_2_PESW_TX0_DN: U34.AP11(RX51_N) ; also on sheet 12
P3E_2_PESW_TX0_DP: U34.AN11(RX51_P) ; also on sheet 12
P3E_2_PESW_TX1_DN: U34.AN10(RX50_N) ; also on sheet 12
P3E_2_PESW_TX1_DP: U34.AM10(RX50_P) ; also on sheet 12
P3E_2_PESW_TX2_DN: U34.AP9(RX49_N) ; also on sheet 12
P3E_2_PESW_TX2_DP: U34.AN9(RX49_P) ; also on sheet 12
P3E_2_PESW_TX3_DN: U34.AN8(RX48_N) ; also on sheet 12
P3E_2_PESW_TX3_DP: U34.AM8(RX48_P) ; also on sheet 12
P3E_3_PESW_RX0_C_DN: C397.2 J49.68
P3E_3_PESW_RX0_C_DP: C398.2 J49.70
P3E_3_PESW_RX0_DN: C397.1 U34.AP37(TX75_N)
P3E_3_PESW_RX0_DP: C398.1 U34.AP36(TX75_P)
P3E_3_PESW_RX1_C_DN: C395.2 J49.76
P3E_3_PESW_RX1_C_DP: C396.2 J49.78
P3E_3_PESW_RX1_DN: C395.1 U34.AR36(TX74_N)
P3E_3_PESW_RX1_DP: C396.1 U34.AR35(TX74_P)
P3E_3_PESW_RX2_C_DN: C393.2 J49.84
P3E_3_PESW_RX2_C_DP: C394.2 J49.86
P3E_3_PESW_RX2_DN: C393.1 U34.AT37(TX73_N)
P3E_3_PESW_RX2_DP: C394.1 U34.AT36(TX73_P)
P3E_3_PESW_RX3_C_DN: C391.2 J49.92
P3E_3_PESW_RX3_C_DP: C392.2 J49.94
P3E_3_PESW_RX3_DN: C391.1 U34.AU36(TX72_N)
P3E_3_PESW_RX3_DP: C392.1 U34.AU35(TX72_P)
P3E_3_PESW_TX0_DN: J49.63 U34.AE37(RX75_N)
P3E_3_PESW_TX0_DP: J49.65 U34.AE36(RX75_P)
P3E_3_PESW_TX1_DN: J49.71 U34.AF36(RX74_N)
P3E_3_PESW_TX1_DP: J49.73 U34.AF35(RX74_P)
P3E_3_PESW_TX2_DN: J49.79 U34.AG37(RX73_N)
P3E_3_PESW_TX2_DP: J49.81 U34.AG36(RX73_P)
P3E_3_PESW_TX3_DN: J49.87 U34.AH36(RX72_N)
P3E_3_PESW_TX3_DP: J49.89 U34.AH35(RX72_P)
P3E_4_PESW_RX0_C_DN: C389.2 J49.102
P3E_4_PESW_RX0_C_DP: C390.2 J49.100
P3E_4_PESW_RX0_DN: C389.1 U34.AU33(TX71_N)
P3E_4_PESW_RX0_DP: C390.1 U34.AT33(TX71_P)
P3E_4_PESW_RX1_C_DN: C387.2 J49.110
P3E_4_PESW_RX1_C_DP: C388.2 J49.108
P3E_4_PESW_RX1_DN: C387.1 U34.AT32(TX70_N)
P3E_4_PESW_RX1_DP: C388.1 U34.AR32(TX70_P)
P3E_4_PESW_RX2_C_DN: C385.2 J49.118
P3E_4_PESW_RX2_C_DP: C386.2 J49.116
P3E_4_PESW_RX2_DN: C385.1 U34.AU31(TX69_N)
P3E_4_PESW_RX2_DP: C386.1 U34.AT31(TX69_P)
P3E_4_PESW_RX3_C_DN: C383.2 J49.126
P3E_4_PESW_RX3_C_DP: C384.2 J49.124
P3E_4_PESW_RX3_DN: C383.1 U34.AT30(TX68_N)
P3E_4_PESW_RX3_DP: C384.1 U34.AR30(TX68_P)
P3E_4_PESW_TX0_DN: J49.95 U34.AP33(RX71_N)
P3E_4_PESW_TX0_DP: J49.97 U34.AN33(RX71_P)
P3E_4_PESW_TX1_DN: J49.103 U34.AN32(RX70_N)
P3E_4_PESW_TX1_DP: J49.105 U34.AM32(RX70_P)
P3E_4_PESW_TX2_DN: J49.111 U34.AP31(RX69_N)
P3E_4_PESW_TX2_DP: J49.113 U34.AN31(RX69_P)
P3E_4_PESW_TX3_DN: J49.119 U34.AN30(RX68_N)
P3E_4_PESW_TX3_DP: J49.121 U34.AM30(RX68_P)
P3E_5_PESW_RX0_C_DN: C381.2 J49.132
P3E_5_PESW_RX0_C_DP: C382.2 J49.134
P3E_5_PESW_RX0_DN: C381.1 U34.AU29(TX67_N)
P3E_5_PESW_RX0_DP: C382.1 U34.AT29(TX67_P)
P3E_5_PESW_RX1_C_DN: C379.2 J49.140
P3E_5_PESW_RX1_C_DP: C380.2 J49.142
P3E_5_PESW_RX1_DN: C379.1 U34.AT28(TX66_N)
P3E_5_PESW_RX1_DP: C380.1 U34.AR28(TX66_P)
P3E_5_PESW_RX2_C_DN: C377.2 J49.148
P3E_5_PESW_RX2_C_DP: C378.2 J49.150
P3E_5_PESW_RX2_DN: C377.1 U34.AU27(TX65_N)
P3E_5_PESW_RX2_DP: C378.1 U34.AT27(TX65_P)
P3E_5_PESW_RX3_C_DN: C407.2 J49.156
P3E_5_PESW_RX3_C_DP: C408.2 J49.158
P3E_5_PESW_RX3_DN: C407.1 U34.AT26(TX64_N)
P3E_5_PESW_RX3_DP: C408.1 U34.AR26(TX64_P)
P3E_5_PESW_TX0_DN: J49.127 U34.AP29(RX67_N)
P3E_5_PESW_TX0_DP: J49.129 U34.AN29(RX67_P)
P3E_5_PESW_TX1_DN: J49.135 U34.AN28(RX66_N)
P3E_5_PESW_TX1_DP: J49.137 U34.AM28(RX66_P)
P3E_5_PESW_TX2_DN: J49.143 U34.AP27(RX65_N)
P3E_5_PESW_TX2_DP: J49.145 U34.AN27(RX65_P)
P3E_5_PESW_TX3_DN: J49.151 U34.AN26(RX64_N)
P3E_5_PESW_TX3_DP: J49.153 U34.AM26(RX64_P)
P3E_6_PESW_RX0_C_DN: C405.2 J49.36
P3E_6_PESW_RX0_C_DP: C406.2 J49.38
P3E_6_PESW_RX0_DN: C405.1 U34.AK37(TX79_N)
P3E_6_PESW_RX0_DP: C406.1 U34.AK36(TX79_P)
P3E_6_PESW_RX1_C_DN: C403.2 J49.44
P3E_6_PESW_RX1_C_DP: C404.2 J49.46
P3E_6_PESW_RX1_DN: C403.1 U34.AL36(TX78_N)
P3E_6_PESW_RX1_DP: C404.1 U34.AL35(TX78_P)
P3E_6_PESW_RX2_C_DN: C401.2 J49.52
P3E_6_PESW_RX2_C_DP: C402.2 J49.54
P3E_6_PESW_RX2_DN: C401.1 U34.AM37(TX77_N)
P3E_6_PESW_RX2_DP: C402.1 U34.AM36(TX77_P)
P3E_6_PESW_RX3_C_DN: C399.2 J49.60
P3E_6_PESW_RX3_C_DP: C400.2 J49.62
P3E_6_PESW_RX3_DN: C399.1 U34.AN36(TX76_N)
P3E_6_PESW_RX3_DP: C400.1 U34.AN35(TX76_P)
P3E_6_PESW_TX0_DN: J49.31 U34.AA37(RX79_N)
P3E_6_PESW_TX0_DP: J49.33 U34.AA36(RX79_P)
P3E_6_PESW_TX1_DN: J49.39 U34.AB36(RX78_N)
P3E_6_PESW_TX1_DP: J49.41 U34.AB35(RX78_P)
P3E_6_PESW_TX2_DN: J49.47 U34.AC37(RX77_N)
P3E_6_PESW_TX2_DP: J49.49 U34.AC36(RX77_P)
P3E_6_PESW_TX3_DN: J49.55 U34.AD36(RX76_N)
P3E_6_PESW_TX3_DP: J49.57 U34.AD35(RX76_P)
P3E_PESW_M2A_RX0_DN: U34.AD6(RX36_P) ; also on sheet 24
P3E_PESW_M2A_RX0_DP: U34.AD5(RX36_N) ; also on sheet 24
P3E_PESW_M2A_RX1_DN: U34.AE5(RX37_P) ; also on sheet 24
P3E_PESW_M2A_RX1_DP: U34.AE4(RX37_N) ; also on sheet 24
P3E_PESW_M2A_RX2_DN: U34.AF6(RX38_P) ; also on sheet 24
P3E_PESW_M2A_RX2_DP: U34.AF5(RX38_N) ; also on sheet 24
P3E_PESW_M2A_RX3_DN: U34.AG5(RX39_P) ; also on sheet 24
P3E_PESW_M2A_RX3_DP: U34.AG4(RX39_N) ; also on sheet 24
P3E_PESW_M2A_TX0_C_DN: C1024.2 ; also on sheet 24
P3E_PESW_M2A_TX0_C_DP: C1023.2 ; also on sheet 24
P3E_PESW_M2A_TX0_DN: C1024.1 U34.AD3(TX36_P)
P3E_PESW_M2A_TX0_DP: C1023.1 U34.AD2(TX36_N)
P3E_PESW_M2A_TX1_C_DN: C1026.2 ; also on sheet 24
P3E_PESW_M2A_TX1_C_DP: C1025.2 ; also on sheet 24
P3E_PESW_M2A_TX1_DN: C1026.1 U34.AE2(TX37_P)
P3E_PESW_M2A_TX1_DP: C1025.1 U34.AE1(TX37_N)
P3E_PESW_M2A_TX2_C_DN: C1028.2 ; also on sheet 24
P3E_PESW_M2A_TX2_C_DP: C1027.2 ; also on sheet 24
P3E_PESW_M2A_TX2_DN: C1028.1 U34.AF3(TX38_P)
P3E_PESW_M2A_TX2_DP: C1027.1 U34.AF2(TX38_N)
P3E_PESW_M2A_TX3_C_DN: C1030.2 ; also on sheet 24
P3E_PESW_M2A_TX3_C_DP: C1029.2 ; also on sheet 24
P3E_PESW_M2A_TX3_DN: C1030.1 U34.AG2(TX39_P)
P3E_PESW_M2A_TX3_DP: C1029.1 U34.AG1(TX39_N)
P3E_PESW_M2B_RX0_DN: U34.Y6(RX32_P) ; also on sheet 25
P3E_PESW_M2B_RX0_DP: U34.Y5(RX32_N) ; also on sheet 25
P3E_PESW_M2B_RX1_DN: U34.AA5(RX33_P) ; also on sheet 25
P3E_PESW_M2B_RX1_DP: U34.AA4(RX33_N) ; also on sheet 25
P3E_PESW_M2B_RX2_DN: U34.AB6(RX34_P) ; also on sheet 25
P3E_PESW_M2B_RX2_DP: U34.AB5(RX34_N) ; also on sheet 25
P3E_PESW_M2B_RX3_DN: U34.AC5(RX35_P) ; also on sheet 25
P3E_PESW_M2B_RX3_DP: U34.AC4(RX35_N) ; also on sheet 25
P3E_PESW_M2B_TX0_C_DN: C1016.2 ; also on sheet 25
P3E_PESW_M2B_TX0_C_DP: C1015.2 ; also on sheet 25
P3E_PESW_M2B_TX0_DN: C1016.1 U34.Y3(TX32_P)
P3E_PESW_M2B_TX0_DP: C1015.1 U34.Y2(TX32_N)
P3E_PESW_M2B_TX1_C_DN: C1018.2 ; also on sheet 25
P3E_PESW_M2B_TX1_C_DP: C1017.2 ; also on sheet 25
P3E_PESW_M2B_TX1_DN: C1018.1 U34.AA2(TX33_P)
P3E_PESW_M2B_TX1_DP: C1017.1 U34.AA1(TX33_N)
P3E_PESW_M2B_TX2_C_DN: C1020.2 ; also on sheet 25
P3E_PESW_M2B_TX2_C_DP: C1019.2 ; also on sheet 25
P3E_PESW_M2B_TX2_DN: C1020.1 U34.AB3(TX34_P)
P3E_PESW_M2B_TX2_DP: C1019.1 U34.AB2(TX34_N)
P3E_PESW_M2B_TX3_C_DN: C1022.2 ; also on sheet 25
P3E_PESW_M2B_TX3_C_DP: C1021.2 ; also on sheet 25
P3E_PESW_M2B_TX3_DN: C1022.1 U34.AC2(TX35_P)
P3E_PESW_M2B_TX3_DP: C1021.1 U34.AC1(TX35_N)
P3E_PESW_M2C_RX0_DN: U34.R5(RX28_P) ; also on sheet 26
P3E_PESW_M2C_RX0_DP: U34.R4(RX28_N) ; also on sheet 26
P3E_PESW_M2C_RX1_DN: U34.T6(RX29_P) ; also on sheet 26
P3E_PESW_M2C_RX1_DP: U34.T5(RX29_N) ; also on sheet 26
P3E_PESW_M2C_RX2_DN: U34.U5(RX30_P) ; also on sheet 26
P3E_PESW_M2C_RX2_DP: U34.U4(RX30_N) ; also on sheet 26
P3E_PESW_M2C_RX3_DN: U34.V6(RX31_P) ; also on sheet 26
P3E_PESW_M2C_RX3_DP: U34.V5(RX31_N) ; also on sheet 26
P3E_PESW_M2C_TX0_C_DN: C432.2 ; also on sheet 26
P3E_PESW_M2C_TX0_C_DP: C431.2 ; also on sheet 26
P3E_PESW_M2C_TX0_DN: C432.1 U34.R2(TX28_P)
P3E_PESW_M2C_TX0_DP: C431.1 U34.R1(TX28_N)
P3E_PESW_M2C_TX1_C_DN: C434.2 ; also on sheet 26
P3E_PESW_M2C_TX1_C_DP: C433.2 ; also on sheet 26
P3E_PESW_M2C_TX1_DN: C434.1 U34.T3(TX29_P)
P3E_PESW_M2C_TX1_DP: C433.1 U34.T2(TX29_N)
P3E_PESW_M2C_TX2_C_DN: C436.2 ; also on sheet 26
P3E_PESW_M2C_TX2_C_DP: C435.2 ; also on sheet 26
P3E_PESW_M2C_TX2_DN: C436.1 U34.U2(TX30_P)
P3E_PESW_M2C_TX2_DP: C435.1 U34.U1(TX30_N)
P3E_PESW_M2C_TX3_C_DN: C438.2 ; also on sheet 26
P3E_PESW_M2C_TX3_C_DP: C437.2 ; also on sheet 26
P3E_PESW_M2C_TX3_DN: C438.1 U34.V3(TX31_P)
P3E_PESW_M2C_TX3_DP: C437.1 U34.V2(TX31_N)
P3E_PESW_M2D_RX0_DN: U34.L5(RX24_P) ; also on sheet 27
P3E_PESW_M2D_RX0_DP: U34.L4(RX24_N) ; also on sheet 27
P3E_PESW_M2D_RX1_DN: U34.M6(RX25_P) ; also on sheet 27
P3E_PESW_M2D_RX1_DP: U34.M5(RX25_N) ; also on sheet 27
P3E_PESW_M2D_RX2_DN: U34.N5(RX26_P) ; also on sheet 27
P3E_PESW_M2D_RX2_DP: U34.N4(RX26_N) ; also on sheet 27
P3E_PESW_M2D_RX3_DN: U34.P6(RX27_P) ; also on sheet 27
P3E_PESW_M2D_RX3_DP: U34.P5(RX27_N) ; also on sheet 27
P3E_PESW_M2D_TX0_C_DN: C424.2 ; also on sheet 27
P3E_PESW_M2D_TX0_C_DP: C423.2 ; also on sheet 27
P3E_PESW_M2D_TX0_DN: C424.1 U34.L2(TX24_P)
P3E_PESW_M2D_TX0_DP: C423.1 U34.L1(TX24_N)
P3E_PESW_M2D_TX1_C_DN: C426.2 ; also on sheet 27
P3E_PESW_M2D_TX1_C_DP: C425.2 ; also on sheet 27
P3E_PESW_M2D_TX1_DN: C426.1 U34.M3(TX25_P)
P3E_PESW_M2D_TX1_DP: C425.1 U34.M2(TX25_N)
P3E_PESW_M2D_TX2_C_DN: C428.2 ; also on sheet 27
P3E_PESW_M2D_TX2_C_DP: C427.2 ; also on sheet 27
P3E_PESW_M2D_TX2_DN: C428.1 U34.N2(TX26_P)
P3E_PESW_M2D_TX2_DP: C427.1 U34.N1(TX26_N)
P3E_PESW_M2D_TX3_C_DN: C430.2 ; also on sheet 27
P3E_PESW_M2D_TX3_C_DP: C429.2 ; also on sheet 27
P3E_PESW_M2D_TX3_DN: C430.1 U34.P3(TX27_P)
P3E_PESW_M2D_TX3_DP: C429.1 U34.P2(TX27_N)
P3E_PESW_M2E_RX0_DN: U34.E11(RX12_P) ; also on sheet 28
P3E_PESW_M2E_RX0_DP: U34.D11(RX12_N) ; also on sheet 28
P3E_PESW_M2E_RX1_DN: U34.F10(RX13_P) ; also on sheet 28
P3E_PESW_M2E_RX1_DP: U34.E10(RX13_N) ; also on sheet 28
P3E_PESW_M2E_RX2_DN: U34.E9(RX14_P) ; also on sheet 28
P3E_PESW_M2E_RX2_DP: U34.D9(RX14_N) ; also on sheet 28
P3E_PESW_M2E_RX3_DN: U34.F8(RX15_P) ; also on sheet 28
P3E_PESW_M2E_RX3_DP: U34.E8(RX15_N) ; also on sheet 28
P3E_PESW_M2E_TX0_C_DN: C905.2 ; also on sheet 28
P3E_PESW_M2E_TX0_C_DP: C904.2 ; also on sheet 28
P3E_PESW_M2E_TX0_DN: C905.1 U34.B11(TX12_P)
P3E_PESW_M2E_TX0_DP: C904.1 U34.A11(TX12_N)
P3E_PESW_M2E_TX1_C_DN: C875.2 ; also on sheet 28
P3E_PESW_M2E_TX1_C_DP: C906.2 ; also on sheet 28
P3E_PESW_M2E_TX1_DN: C875.1 U34.C10(TX13_P)
P3E_PESW_M2E_TX1_DP: C906.1 U34.B10(TX13_N)
P3E_PESW_M2E_TX2_C_DN: C877.2 ; also on sheet 28
P3E_PESW_M2E_TX2_C_DP: C876.2 ; also on sheet 28
P3E_PESW_M2E_TX2_DN: C877.1 U34.B9(TX14_P)
P3E_PESW_M2E_TX2_DP: C876.1 U34.A9(TX14_N)
P3E_PESW_M2E_TX3_C_DN: C879.2 ; also on sheet 28
P3E_PESW_M2E_TX3_C_DP: C878.2 ; also on sheet 28
P3E_PESW_M2E_TX3_DN: C879.1 U34.C8(TX15_P)
P3E_PESW_M2E_TX3_DP: C878.1 U34.B8(TX15_N)
P3E_PESW_M2F_RX0_DN: U34.E15(RX8_P) ; also on sheet 29
P3E_PESW_M2F_RX0_DP: U34.D15(RX8_N) ; also on sheet 29
P3E_PESW_M2F_RX1_DN: U34.F14(RX9_P) ; also on sheet 29
P3E_PESW_M2F_RX1_DP: U34.E14(RX9_N) ; also on sheet 29
P3E_PESW_M2F_RX2_DN: U34.E13(RX10_P) ; also on sheet 29
P3E_PESW_M2F_RX2_DP: U34.D13(RX10_N) ; also on sheet 29
P3E_PESW_M2F_RX3_DN: U34.F12(RX11_P) ; also on sheet 29
P3E_PESW_M2F_RX3_DP: U34.E12(RX11_N) ; also on sheet 29
P3E_PESW_M2F_TX0_C_DN: C897.2 ; also on sheet 29
P3E_PESW_M2F_TX0_C_DP: C896.2 ; also on sheet 29
P3E_PESW_M2F_TX0_DN: C897.1 U34.B15(TX8_P)
P3E_PESW_M2F_TX0_DP: C896.1 U34.A15(TX8_N)
P3E_PESW_M2F_TX1_C_DN: C899.2 ; also on sheet 29
P3E_PESW_M2F_TX1_C_DP: C898.2 ; also on sheet 29
P3E_PESW_M2F_TX1_DN: C899.1 U34.C14(TX9_P)
P3E_PESW_M2F_TX1_DP: C898.1 U34.B14(TX9_N)
P3E_PESW_M2F_TX2_C_DN: C901.2 ; also on sheet 29
P3E_PESW_M2F_TX2_C_DP: C900.2 ; also on sheet 29
P3E_PESW_M2F_TX2_DN: C901.1 U34.B13(TX10_P)
P3E_PESW_M2F_TX2_DP: C900.1 U34.A13(TX10_N)
P3E_PESW_M2F_TX3_C_DN: C903.2 ; also on sheet 29
P3E_PESW_M2F_TX3_C_DP: C902.2 ; also on sheet 29
P3E_PESW_M2F_TX3_DN: C903.1 U34.C12(TX11_P)
P3E_PESW_M2F_TX3_DP: C902.1 U34.B12(TX11_N)
P3E_PESW_M2G_RX0_DN: U34.E21(RX3_N) ; also on sheet 30
P3E_PESW_M2G_RX0_DP: U34.F21(RX3_P) ; also on sheet 30
P3E_PESW_M2G_RX1_DN: U34.D22(RX2_N) ; also on sheet 30
P3E_PESW_M2G_RX1_DP: U34.E22(RX2_P) ; also on sheet 30
P3E_PESW_M2G_RX2_DN: U34.E23(RX1_N) ; also on sheet 30
P3E_PESW_M2G_RX2_DP: U34.F23(RX1_P) ; also on sheet 30
P3E_PESW_M2G_RX3_DN: U34.D24(RX0_N) ; also on sheet 30
P3E_PESW_M2G_RX3_DP: U34.E24(RX0_P) ; also on sheet 30
P3E_PESW_M2G_TX0_C_DN: C886.2 ; also on sheet 30
P3E_PESW_M2G_TX0_C_DP: C887.2 ; also on sheet 30
P3E_PESW_M2G_TX0_DN: C886.1 U34.B21(TX3_N)
P3E_PESW_M2G_TX0_DP: C887.1 U34.C21(TX3_P)
P3E_PESW_M2G_TX1_C_DN: C884.2 ; also on sheet 30
P3E_PESW_M2G_TX1_C_DP: C885.2 ; also on sheet 30
P3E_PESW_M2G_TX1_DN: C884.1 U34.A22(TX2_N)
P3E_PESW_M2G_TX1_DP: C885.1 U34.B22(TX2_P)
P3E_PESW_M2G_TX2_C_DN: C882.2 ; also on sheet 30
P3E_PESW_M2G_TX2_C_DP: C883.2 ; also on sheet 30
P3E_PESW_M2G_TX2_DN: C882.1 U34.B23(TX1_N)
P3E_PESW_M2G_TX2_DP: C883.1 U34.C23(TX1_P)
P3E_PESW_M2G_TX3_C_DN: C880.2 ; also on sheet 30
P3E_PESW_M2G_TX3_C_DP: C881.2 ; also on sheet 30
P3E_PESW_M2G_TX3_DN: C880.1 U34.A24(TX0_N)
P3E_PESW_M2G_TX3_DP: C881.1 U34.B24(TX0_P)
P3E_PESW_M2H_RX0_DN: U34.E17(RX7_N) ; also on sheet 31
P3E_PESW_M2H_RX0_DP: U34.F17(RX7_P) ; also on sheet 31
P3E_PESW_M2H_RX1_DN: U34.D18(RX6_N) ; also on sheet 31
P3E_PESW_M2H_RX1_DP: U34.E18(RX6_P) ; also on sheet 31
P3E_PESW_M2H_RX2_DN: U34.E19(RX5_N) ; also on sheet 31
P3E_PESW_M2H_RX2_DP: U34.F19(RX5_P) ; also on sheet 31
P3E_PESW_M2H_RX3_DN: U34.D20(RX4_N) ; also on sheet 31
P3E_PESW_M2H_RX3_DP: U34.E20(RX4_P) ; also on sheet 31
P3E_PESW_M2H_TX0_C_DN: C894.2 ; also on sheet 31
P3E_PESW_M2H_TX0_C_DP: C895.2 ; also on sheet 31
P3E_PESW_M2H_TX0_DN: C894.1 U34.B17(TX7_N)
P3E_PESW_M2H_TX0_DP: C895.1 U34.C17(TX7_P)
P3E_PESW_M2H_TX1_C_DN: C892.2 ; also on sheet 31
P3E_PESW_M2H_TX1_C_DP: C893.2 ; also on sheet 31
P3E_PESW_M2H_TX1_DN: C892.1 U34.A18(TX6_N)
P3E_PESW_M2H_TX1_DP: C893.1 U34.B18(TX6_P)
P3E_PESW_M2H_TX2_C_DN: C890.2 ; also on sheet 31
P3E_PESW_M2H_TX2_C_DP: C891.2 ; also on sheet 31
P3E_PESW_M2H_TX2_DN: C890.1 U34.B19(TX5_N)
P3E_PESW_M2H_TX2_DP: C891.1 U34.C19(TX5_P)
P3E_PESW_M2H_TX3_C_DN: C888.2 ; also on sheet 31
P3E_PESW_M2H_TX3_C_DP: C889.2 ; also on sheet 31
P3E_PESW_M2H_TX3_DN: C888.1 U34.A20(TX4_N)
P3E_PESW_M2H_TX3_DP: C889.1 U34.B20(TX4_P)
P3E_PESW_M2I_RX0_DN: U34.E5(RX19_N) ; also on sheet 32
P3E_PESW_M2I_RX0_DP: U34.E6(RX19_P) ; also on sheet 32
P3E_PESW_M2I_RX1_DN: U34.D4(RX18_N) ; also on sheet 32
P3E_PESW_M2I_RX1_DP: U34.D5(RX18_P) ; also on sheet 32
P3E_PESW_M2I_RX2_DN: U34.C5(RX17_N) ; also on sheet 32
P3E_PESW_M2I_RX2_DP: U34.C6(RX17_P) ; also on sheet 32
P3E_PESW_M2I_RX3_DN: U34.B4(RX16_N) ; also on sheet 32
P3E_PESW_M2I_RX3_DP: U34.B5(RX16_P) ; also on sheet 32
P3E_PESW_M2I_TX0_C_DN: C413.2 ; also on sheet 32
P3E_PESW_M2I_TX0_C_DP: C414.2 ; also on sheet 32
P3E_PESW_M2I_TX0_DN: C413.1 U34.E2(TX19_N)
P3E_PESW_M2I_TX0_DP: C414.1 U34.E3(TX19_P)
P3E_PESW_M2I_TX1_C_DN: C411.2 ; also on sheet 32
P3E_PESW_M2I_TX1_C_DP: C412.2 ; also on sheet 32
P3E_PESW_M2I_TX1_DN: C411.1 U34.D1(TX18_N)
P3E_PESW_M2I_TX1_DP: C412.1 U34.D2(TX18_P)
P3E_PESW_M2I_TX2_C_DN: C409.2 ; also on sheet 32
P3E_PESW_M2I_TX2_C_DP: C410.2 ; also on sheet 32
P3E_PESW_M2I_TX2_DN: C409.1 U34.C2(TX17_N)
P3E_PESW_M2I_TX2_DP: C410.1 U34.C3(TX17_P)
P3E_PESW_M2I_TX3_C_DN: C439.2 ; also on sheet 32
P3E_PESW_M2I_TX3_C_DP: C440.2 ; also on sheet 32
P3E_PESW_M2I_TX3_DN: C439.1 U34.B1(TX16_N)
P3E_PESW_M2I_TX3_DP: C440.1 U34.B2(TX16_P)
P3E_PESW_M2J_RX0_DN: U34.J5(RX23_N) ; also on sheet 33
P3E_PESW_M2J_RX0_DP: U34.J6(RX23_P) ; also on sheet 33
P3E_PESW_M2J_RX1_DN: U34.H4(RX22_N) ; also on sheet 33
P3E_PESW_M2J_RX1_DP: U34.H5(RX22_P) ; also on sheet 33
P3E_PESW_M2J_RX2_DN: U34.G5(RX21_N) ; also on sheet 33
P3E_PESW_M2J_RX2_DP: U34.G6(RX21_P) ; also on sheet 33
P3E_PESW_M2J_RX3_DN: U34.F4(RX20_N) ; also on sheet 33
P3E_PESW_M2J_RX3_DP: U34.F5(RX20_P) ; also on sheet 33
P3E_PESW_M2J_TX0_C_DN: C421.2 ; also on sheet 33
P3E_PESW_M2J_TX0_C_DP: C422.2 ; also on sheet 33
P3E_PESW_M2J_TX0_DN: C421.1 U34.J2(TX23_N)
P3E_PESW_M2J_TX0_DP: C422.1 U34.J3(TX23_P)
P3E_PESW_M2J_TX1_C_DN: C419.2 ; also on sheet 33
P3E_PESW_M2J_TX1_C_DP: C420.2 ; also on sheet 33
P3E_PESW_M2J_TX1_DN: C419.1 U34.H1(TX22_N)
P3E_PESW_M2J_TX1_DP: C420.1 U34.H2(TX22_P)
P3E_PESW_M2J_TX2_C_DN: C417.2 ; also on sheet 33
P3E_PESW_M2J_TX2_C_DP: C418.2 ; also on sheet 33
P3E_PESW_M2J_TX2_DN: C417.1 U34.G2(TX21_N)
P3E_PESW_M2J_TX2_DP: C418.1 U34.G3(TX21_P)
P3E_PESW_M2J_TX3_C_DN: C415.2 ; also on sheet 33
P3E_PESW_M2J_TX3_C_DP: C416.2 ; also on sheet 33
P3E_PESW_M2J_TX3_DN: C415.1 U34.F1(TX20_N)
P3E_PESW_M2J_TX3_DP: C416.1 U34.F2(TX20_P)
P3E_PESW_M2K_RX0_DN: U34.AM4(RX43_N) ; also on sheet 34
P3E_PESW_M2K_RX0_DP: U34.AM5(RX43_P) ; also on sheet 34
P3E_PESW_M2K_RX1_DN: U34.AL5(RX42_N) ; also on sheet 34
P3E_PESW_M2K_RX1_DP: U34.AL6(RX42_P) ; also on sheet 34
P3E_PESW_M2K_RX2_DN: U34.AK4(RX41_N) ; also on sheet 34
P3E_PESW_M2K_RX2_DP: U34.AK5(RX41_P) ; also on sheet 34
P3E_PESW_M2K_RX3_DN: U34.AJ5(RX40_N) ; also on sheet 34
P3E_PESW_M2K_RX3_DP: U34.AJ6(RX40_P) ; also on sheet 34
P3E_PESW_M2K_TX0_C_DN: C1037.2 ; also on sheet 34
P3E_PESW_M2K_TX0_C_DP: C1038.2 ; also on sheet 34
P3E_PESW_M2K_TX0_DN: C1037.1 U34.AM1(TX43_N)
P3E_PESW_M2K_TX0_DP: C1038.1 U34.AM2(TX43_P)
P3E_PESW_M2K_TX1_C_DN: C1035.2 ; also on sheet 34
P3E_PESW_M2K_TX1_C_DP: C1036.2 ; also on sheet 34
P3E_PESW_M2K_TX1_DN: C1035.1 U34.AL2(TX42_N)
P3E_PESW_M2K_TX1_DP: C1036.1 U34.AL3(TX42_P)
P3E_PESW_M2K_TX2_C_DN: C1033.2 ; also on sheet 34
P3E_PESW_M2K_TX2_C_DP: C1034.2 ; also on sheet 34
P3E_PESW_M2K_TX2_DN: C1033.1 U34.AK1(TX41_N)
P3E_PESW_M2K_TX2_DP: C1034.1 U34.AK2(TX41_P)
P3E_PESW_M2K_TX3_C_DN: C1031.2 ; also on sheet 34
P3E_PESW_M2K_TX3_C_DP: C1032.2 ; also on sheet 34
P3E_PESW_M2K_TX3_DN: C1031.1 U34.AJ2(TX40_N)
P3E_PESW_M2K_TX3_DP: C1032.1 U34.AJ3(TX40_P)
P3E_PESW_M2L_RX0_DN: U34.AT4(RX47_N) ; also on sheet 35
P3E_PESW_M2L_RX0_DP: U34.AT5(RX47_P) ; also on sheet 35
P3E_PESW_M2L_RX1_DN: U34.AR5(RX46_N) ; also on sheet 35
P3E_PESW_M2L_RX1_DP: U34.AR6(RX46_P) ; also on sheet 35
P3E_PESW_M2L_RX2_DN: U34.AP4(RX45_N) ; also on sheet 35
P3E_PESW_M2L_RX2_DP: U34.AP5(RX45_P) ; also on sheet 35
P3E_PESW_M2L_RX3_DN: U34.AN5(RX44_N) ; also on sheet 35
P3E_PESW_M2L_RX3_DP: U34.AN6(RX44_P) ; also on sheet 35
P3E_PESW_M2L_TX0_C_DN: C1013.2 ; also on sheet 35
P3E_PESW_M2L_TX0_C_DP: C1014.2 ; also on sheet 35
P3E_PESW_M2L_TX0_DN: C1013.1 U34.AT1(TX47_N)
P3E_PESW_M2L_TX0_DP: C1014.1 U34.AT2(TX47_P)
P3E_PESW_M2L_TX1_C_DN: C1011.2 ; also on sheet 35
P3E_PESW_M2L_TX1_C_DP: C1012.2 ; also on sheet 35
P3E_PESW_M2L_TX1_DN: C1011.1 U34.AR2(TX46_N)
P3E_PESW_M2L_TX1_DP: C1012.1 U34.AR3(TX46_P)
P3E_PESW_M2L_TX2_C_DN: C1041.2 ; also on sheet 35
P3E_PESW_M2L_TX2_C_DP: C1010.2 ; also on sheet 35
P3E_PESW_M2L_TX2_DN: C1041.1 U34.AP1(TX45_N)
P3E_PESW_M2L_TX2_DP: C1010.1 U34.AP2(TX45_P)
P3E_PESW_M2L_TX3_C_DN: C1039.2 ; also on sheet 35
P3E_PESW_M2L_TX3_C_DP: C1040.2 ; also on sheet 35
P3E_PESW_M2L_TX3_DN: C1039.1 U34.AN2(TX44_N)
P3E_PESW_M2L_TX3_DP: C1040.1 U34.AN3(TX44_P)
PD_BOOTSTRAP_1: R3136.1 R3159.2 U34.W35(GPIO_97)
PD_BOOTSTRAP_2: R3137.1 R3158.2 U34.W34(GPIO_98)
PD_BOOTSTRAP_4: R3139.1 R3156.2 U34.Y34(GPIO_100)
PD_BOOTSTRAP_5: R3140.1 R3155.2 U34.W36(GPIO_101)
PD_BOOTSTRAP_6: R3142.1 R3154.2 U34.W27(GPIO_102)
PD_BOOTSTRAP_7: R3143.1 R3153.2 U34.W31(GPIO_103)
PD_BOOTSTRAP_8: R3144.1 R3152.2 U34.Y28(GPIO_104)
PD_BOOTSTRAP_9: R3145.1 R3151.2 U34.Y27(GPIO_105)
PD_TPIN: R3257.2 U34.R29(TPIN)
PD_UART_PESW_UCTSB: R3256.2 U34.T27(UART_UCTSB)
PU_BOOTSTRAP_0: R3141.1 R3160.2 U34.V34(GPIO_96)
PU_BOOTSTRAP_3: R3138.1 R3157.2 U34.W37(GPIO_99)
PU_BOOTSTRAP_10: R3146.1 R3150.2 U34.AA27(GPIO_106)
PU_TAP_SEL: R3147.1 R3149.2 U34.AG30(TAP_SEL)
RST_PE_PESW_GPIO15_N: U34.N30(TWI_SRSTB_7) ; also on sheet 67
RST_PE_PESW_GPIO28_N: U34.L33(TWI_SCL_8) ; also on sheet 67
RST_PE_PESW_GPIO29_N: U34.M28(TWI_SDA_8) ; also on sheet 67
RST_PE_PESW_GPIO30_N: U34.M30(TWI_SRSTB_8) ; also on sheet 67
RST_PE_PESW_GPIO31_N: U34.N28(TWI_SCL_7) ; also on sheet 67
RST_PE_PESW_GPIO35_N: U34.N31(TWI_SDA_7) ; also on sheet 67
RST_PESW_M2A_N: R3287.2 ; also on sheet 44
RST_PESW_M2A_N_R: R3287.1 U34.AE33(GPIO_92)
RST_PESW_M2B_N: R3288.2 ; also on sheet 44
RST_PESW_M2B_N_R: R3288.1 U34.AE31(GPIO_93)
RST_PESW_M2C_N: R3289.2 ; also on sheet 44
RST_PESW_M2C_N_R: R3289.1 U34.U30(GPIO_82)
RST_PESW_M2D_N: R3290.2 ; also on sheet 44
RST_PESW_M2D_N_R: R3290.1 U34.AB28(GPIO_83)
RST_PESW_M2E_N: R3291.2 ; also on sheet 44
RST_PESW_M2E_N_R: R3291.1 U34.AB27(GPIO_84)
RST_PESW_M2F_N: R3292.2 ; also on sheet 44
RST_PESW_M2F_N_R: R3292.1 U34.AC31(GPIO_85)
RST_PESW_M2G_N: R3293.2 ; also on sheet 44
RST_PESW_M2G_N_R: R3293.1 U34.AC28(GPIO_86)
RST_PESW_M2H_N: R3294.2 ; also on sheet 44
RST_PESW_M2H_N_R: R3294.1 U34.AC27(GPIO_87)
RST_PESW_M2I_N: R3295.2 ; also on sheet 44
RST_PESW_M2I_N_R: R3295.1 U34.AD31(GPIO_88)
RST_PESW_M2J_N: R3296.2 ; also on sheet 44
RST_PESW_M2J_N_R: R3296.1 U34.AD30(GPIO_89)
RST_PESW_M2K_N: R3297.2 ; also on sheet 44
RST_PESW_M2K_N_R: R3297.1 U34.AD29(GPIO_90)
RST_PESW_M2L_N: R3298.2 ; also on sheet 44
RST_PESW_M2L_N_R: R3298.1 U34.AD27(GPIO_91)
SMB_PESW_P1V8_CLK: R4049.1 ; also on sheet 23
SMB_PESW_P1V8_CLK_R2: R3336.1 R4049.2 U34.K27(TWI_SCL_1)
SMB_PESW_P1V8_DAT: R4050.1 ; also on sheet 23
SMB_PESW_P1V8_DAT_R2: R3337.1 R4050.2 U34.K30(TWI_SDA_1)
SPI_PESW_FLASH_CLK: R3250.2 ; also on sheet 62
SPI_PESW_FLASH_CLK_R: R3250.1 U34.AJ31(QSPI_CLK)
SPI_PESW_FLASH_CSB_0: R3251.2 ; also on sheet 62
SPI_PESW_FLASH_CSB_0_R: R3251.1 U34.AJ27(QSPI_CSB_0)
SPI_PESW_FLASH_DAT_0: R3252.2 ; also on sheet 62
SPI_PESW_FLASH_DAT_0_R1: R3252.1 U34.AJ29(QSPI_DATA_0)
SPI_PESW_FLASH_DAT_1: R3253.2 ; also on sheet 62
SPI_PESW_FLASH_DAT_1_R1: R3253.1 U34.AJ30(QSPI_DATA_1)
SPI_PESW_FLASH_DAT_2: R3254.2 ; also on sheet 62
SPI_PESW_FLASH_DAT_2_R1: R3254.1 U34.AJ32(QSPI_DATA_2)
SPI_PESW_FLASH_DAT_3: R3255.2 ; also on sheet 62
SPI_PESW_FLASH_DAT_3_R1: R3255.1 U34.AJ33(QSPI_DATA_3)
TP_RESERVED_USB+: J49.25 TP61.1
TP_RESERVED_USB-: J49.27 TP62.1
TWI_PESW_EEPROM_CLK_0: R3260.1 U34.J31(TWI_SCL_0) ; also on sheet 62
TWI_PESW_EEPROM_DAT_0: R3261.1 U34.J32(TWI_SDA_0) ; also on sheet 62
UART_PESW_USIN: U34.R32(UART_USIN) ; also on sheet 18
UART_PESW_USOUT: U34.R31(UART_USOUT) ; also on sheet 18

Not connected (* = marked no-connect by the designer): J49 13 14 30 159; Q10 3(D2)*; U34 A27(NC)* A29(NC)* A31(NC)* A33(NC)* A35(NC)* A36(NC)* AE27(RMII_TX_EN)* AE28(GPIO_95)* AE30(GPIO_94)* AF27(RMII_CRS_DV)* AF28(RMII_REF_CLK)* AF29(RMII_RXD_1)* AF30(RMII_RXD_0)* AF31(RMII_RX_ER)* AF32(RMII_TXD_1)* AF33(RMII_TXD_0)* AH26(LINK)* AH27(MDIO)* AH30(MDC)* AJ28(QSPI_CSB_1)* AK27(GPIO_68)* AK28(GPIO_69)* AK29(GPIO_70)* AK30(GPIO_71)* AK31(GPIO_72)* AK32(GPIO_73)* AK33(GPIO_74)* AM17(RX56_P)* AM19(RX58_P)* AM21(RX60_P)* AM23(RX62_P)* AN17(RX56_N)* AN18(RX57_P)* AN19(RX58_N)* AN20(RX59_P)* AN21(RX60_N)* AN22(RX61_P)* AN23(RX62_N)* AN24(RX63_P)* AP18(RX57_N)* AP20(RX59_N)* AP22(RX61_N)* AP24(RX63_N)* AR17(TX56_P)* AR19(TX58_P)* AR21(TX60_P)* AR23(TX62_P)* AT17(TX56_N)* AT18(TX57_P)* AT19(TX58_N)* AT20(TX59_P)* AT21(TX60_N)* AT22(TX61_P)* AT23(TX62_N)* AT24(TX63_P)* AU18(TX57_N)* AU20(TX59_N)* AU22(TX61_N)* AU24(TX63_N)* B26(NC)* B27(NC)* B28(NC)* B29(NC)* B30(NC)* B31(NC)* B32(NC)* B33(NC)* B36(NC)* B37(NC)* C26(NC)* C28(NC)* C30(NC)* C32(NC)* C35(NC)* C36(NC)* D27(NC)* D29(NC)* D31(NC)* D33(NC)* D36(NC)* D37(NC)* E26(NC)* E27(NC)* E28(NC)* E29(NC)* E30(NC)* E31(NC)* E32(NC)* E33(NC)* E35(NC)* E36(NC)* F26(NC)* F28(NC)* F30(NC)* F32(NC)* F36(NC)* F37(NC)* G35(NC)* G36(NC)* H36(NC)* H37(NC)* J33(TWI_SRSTB_0)* K28(TWI_SCL_2)* K31(TWI_SRSTB_1)* K33(TWI_SDA_2)* K35(NC)* K36(NC)* L26(GPIO_107)* L27(GPIO_108)* L28(TWI_SRSTB_2)* L32(GPIO_109)* L36(NC)* L37(NC)* M29(TWI_SCL_9)* M33(TWI_SDA_9)* M35(NC)* M36(NC)* N27(TWI_SRSTB_9)* N32(TWI_SCL_10)* N33(TWI_SDA_10)* N36(NC)* N37(NC)* P35(NC)* P36(NC)* R36(NC)* R37(NC)* T28(UART_URTSB)* T35(NC)* T36(NC)* U27(GPIO_67)* U28(GPIO_65)* U29(GPIO_66)* U32(GPIO_81)* U33(GPIO_79)* U36(NC)* U37(NC)* V27(GPIO_80)* V29(GPIO_77)* V30(GPIO_75)* V31(GPIO_76)* V33(GPIO_78)*

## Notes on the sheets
sheet 13
- Note: Reserved USB2 (PIN25.27) port
- Polarity Reversal for layout purpose
- Polarity Reversal for layout purpose
- Polarity Reversal for layout purpose
- Polarity Reversal for layout purpose
- Polarity Reversal for layout purpose
- Polarity Reversal for layout purpose
- Polarity Reversal for layout purpose
- MEZZ CONN EXTENSION
sheet 14
- BOM Note:
  U34 change to PM8545B-FEI
- Stack 1
- Lane Reversal for layout purpose
- Lane Reversal for layout purpose
- Lane Reversal for layout purpose
- Lane Reversal for layout purpose
- Polarity Reversal for layout purpose
- Polarity Reversal for layout purpose
- Polarity Reversal for layout purpose
- Polarity Reversal for layout purpose
- Stack 2
- Lane Reversal for layout purpose
- Lane Reversal for layout purpose
- Lane Reversal for layout purpose
- Lane Reversal for layout purpose
- Polarity Reversal for layout purpose
- Polarity Reversal for layout purpose
- Polarity Reversal for layout purpose
- Polarity Reversal for layout purpose
- PCIE SWITCH (STACK1-2)
sheet 15
- BOM Note:
  U34 change to PM8545B-FEI
- Stack 3
- Polarity Reversal for layout purpose
- Polarity Reversal for layout purpose
- Polarity Reversal for layout purpose
- Polarity Reversal for layout purpose
- Lane Reversal for layout purpose
- Lane Reversal for layout purpose
- Lane Reversal for layout purpose
- Lane Reversal for layout purpose
- Stack 4
- Lane Reversal for layout purpose
- Lane Reversal for layout purpose
- Lane Reversal for layout purpose
- Lane Reversal for layout purpose
- PCIE SWITCH (STACK3-4)
sheet 16
- BOM Note:
  U34 change to PM8545B-FEI
- Stack 5
- Lane Reversal for layout purpose
- Lane Reversal for layout purpose
- Lane Reversal for layout purpose
- Lane Reversal for layout purpose
- Lane Reversal for layout purpose
- Lane Reversal for layout purpose
- Lane Reversal for layout purpose
- Lane Reversal for layout purpose
- PCIE SWITCH (STACK5)
sheet 17
- BOM Note:
  U34 change to PM8545B-FEI
- M.2 A-L Power enable
- M.2 A-L Reset
- Note:
  Unsed TWI pins will set to GPIO mode.
- SPEC Revision:13(2018/2)
- HEART BEAT LED
- PCIE SWITCH (GPIO)
